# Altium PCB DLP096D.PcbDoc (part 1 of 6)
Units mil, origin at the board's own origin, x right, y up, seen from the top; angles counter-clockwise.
Board outline 4950 x 3159.45 mil, 8 copper layers (Top Layer, GND1, SIGNAL1, POWER1, POWER2, SIGNAL2, GND2, Bottom Layer), stack 60.4 mil thick; 328 components, 223 nets, 1380 pads, 856 vias.
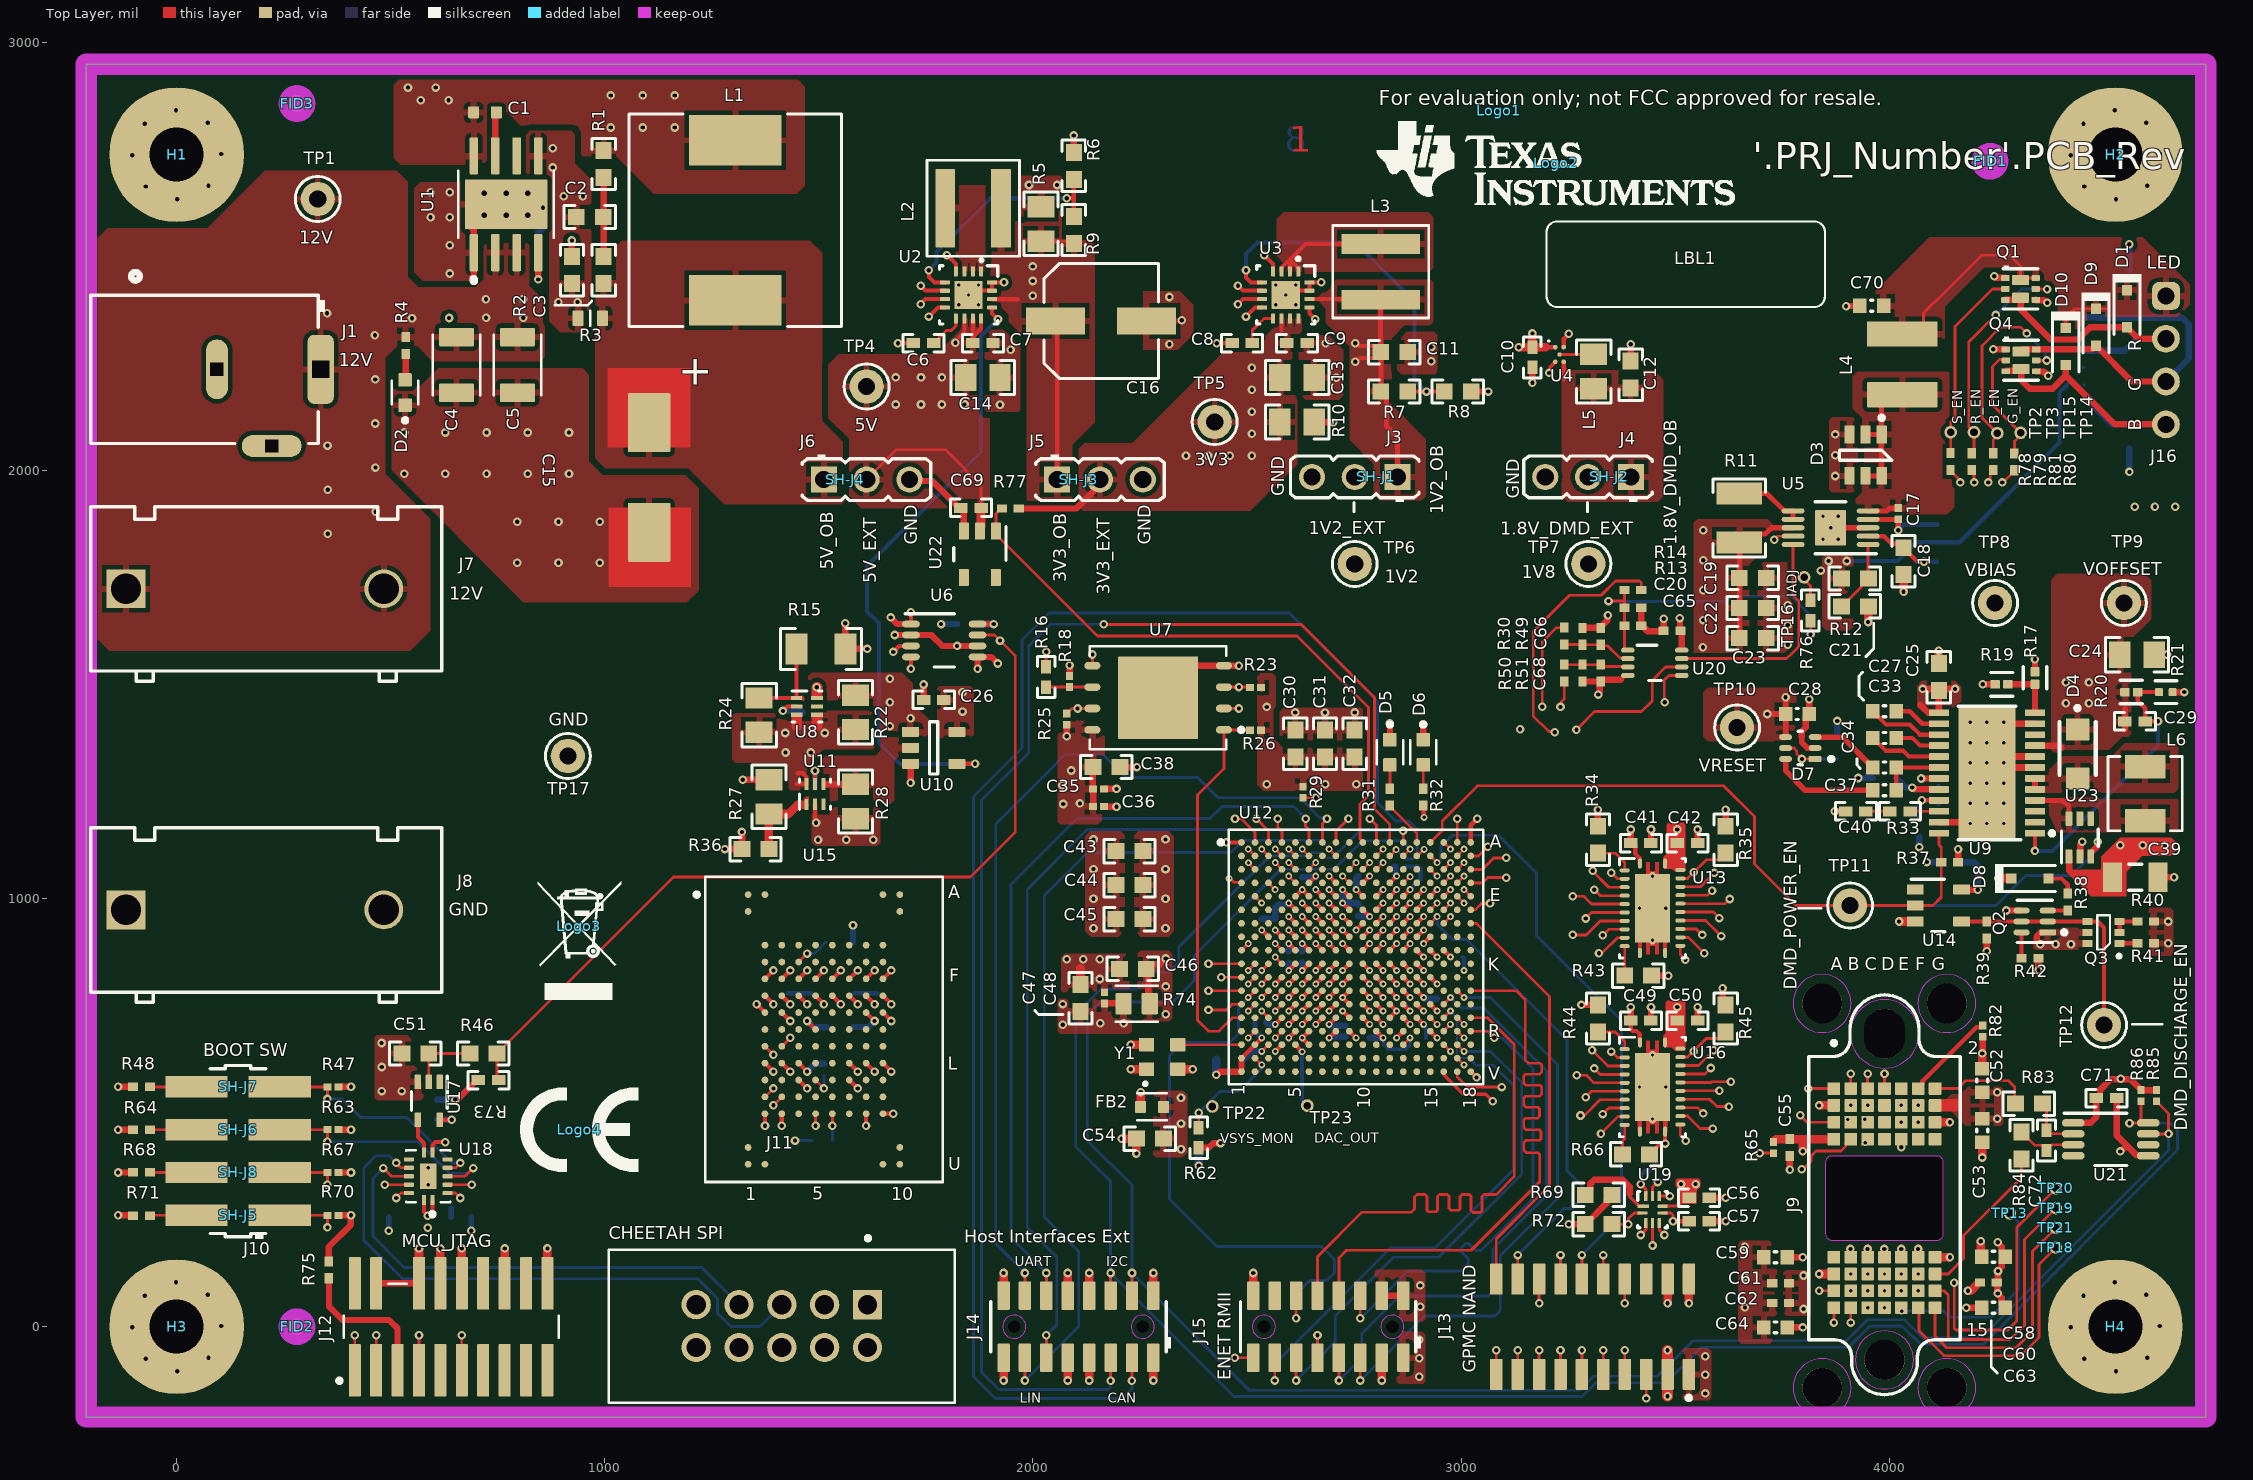
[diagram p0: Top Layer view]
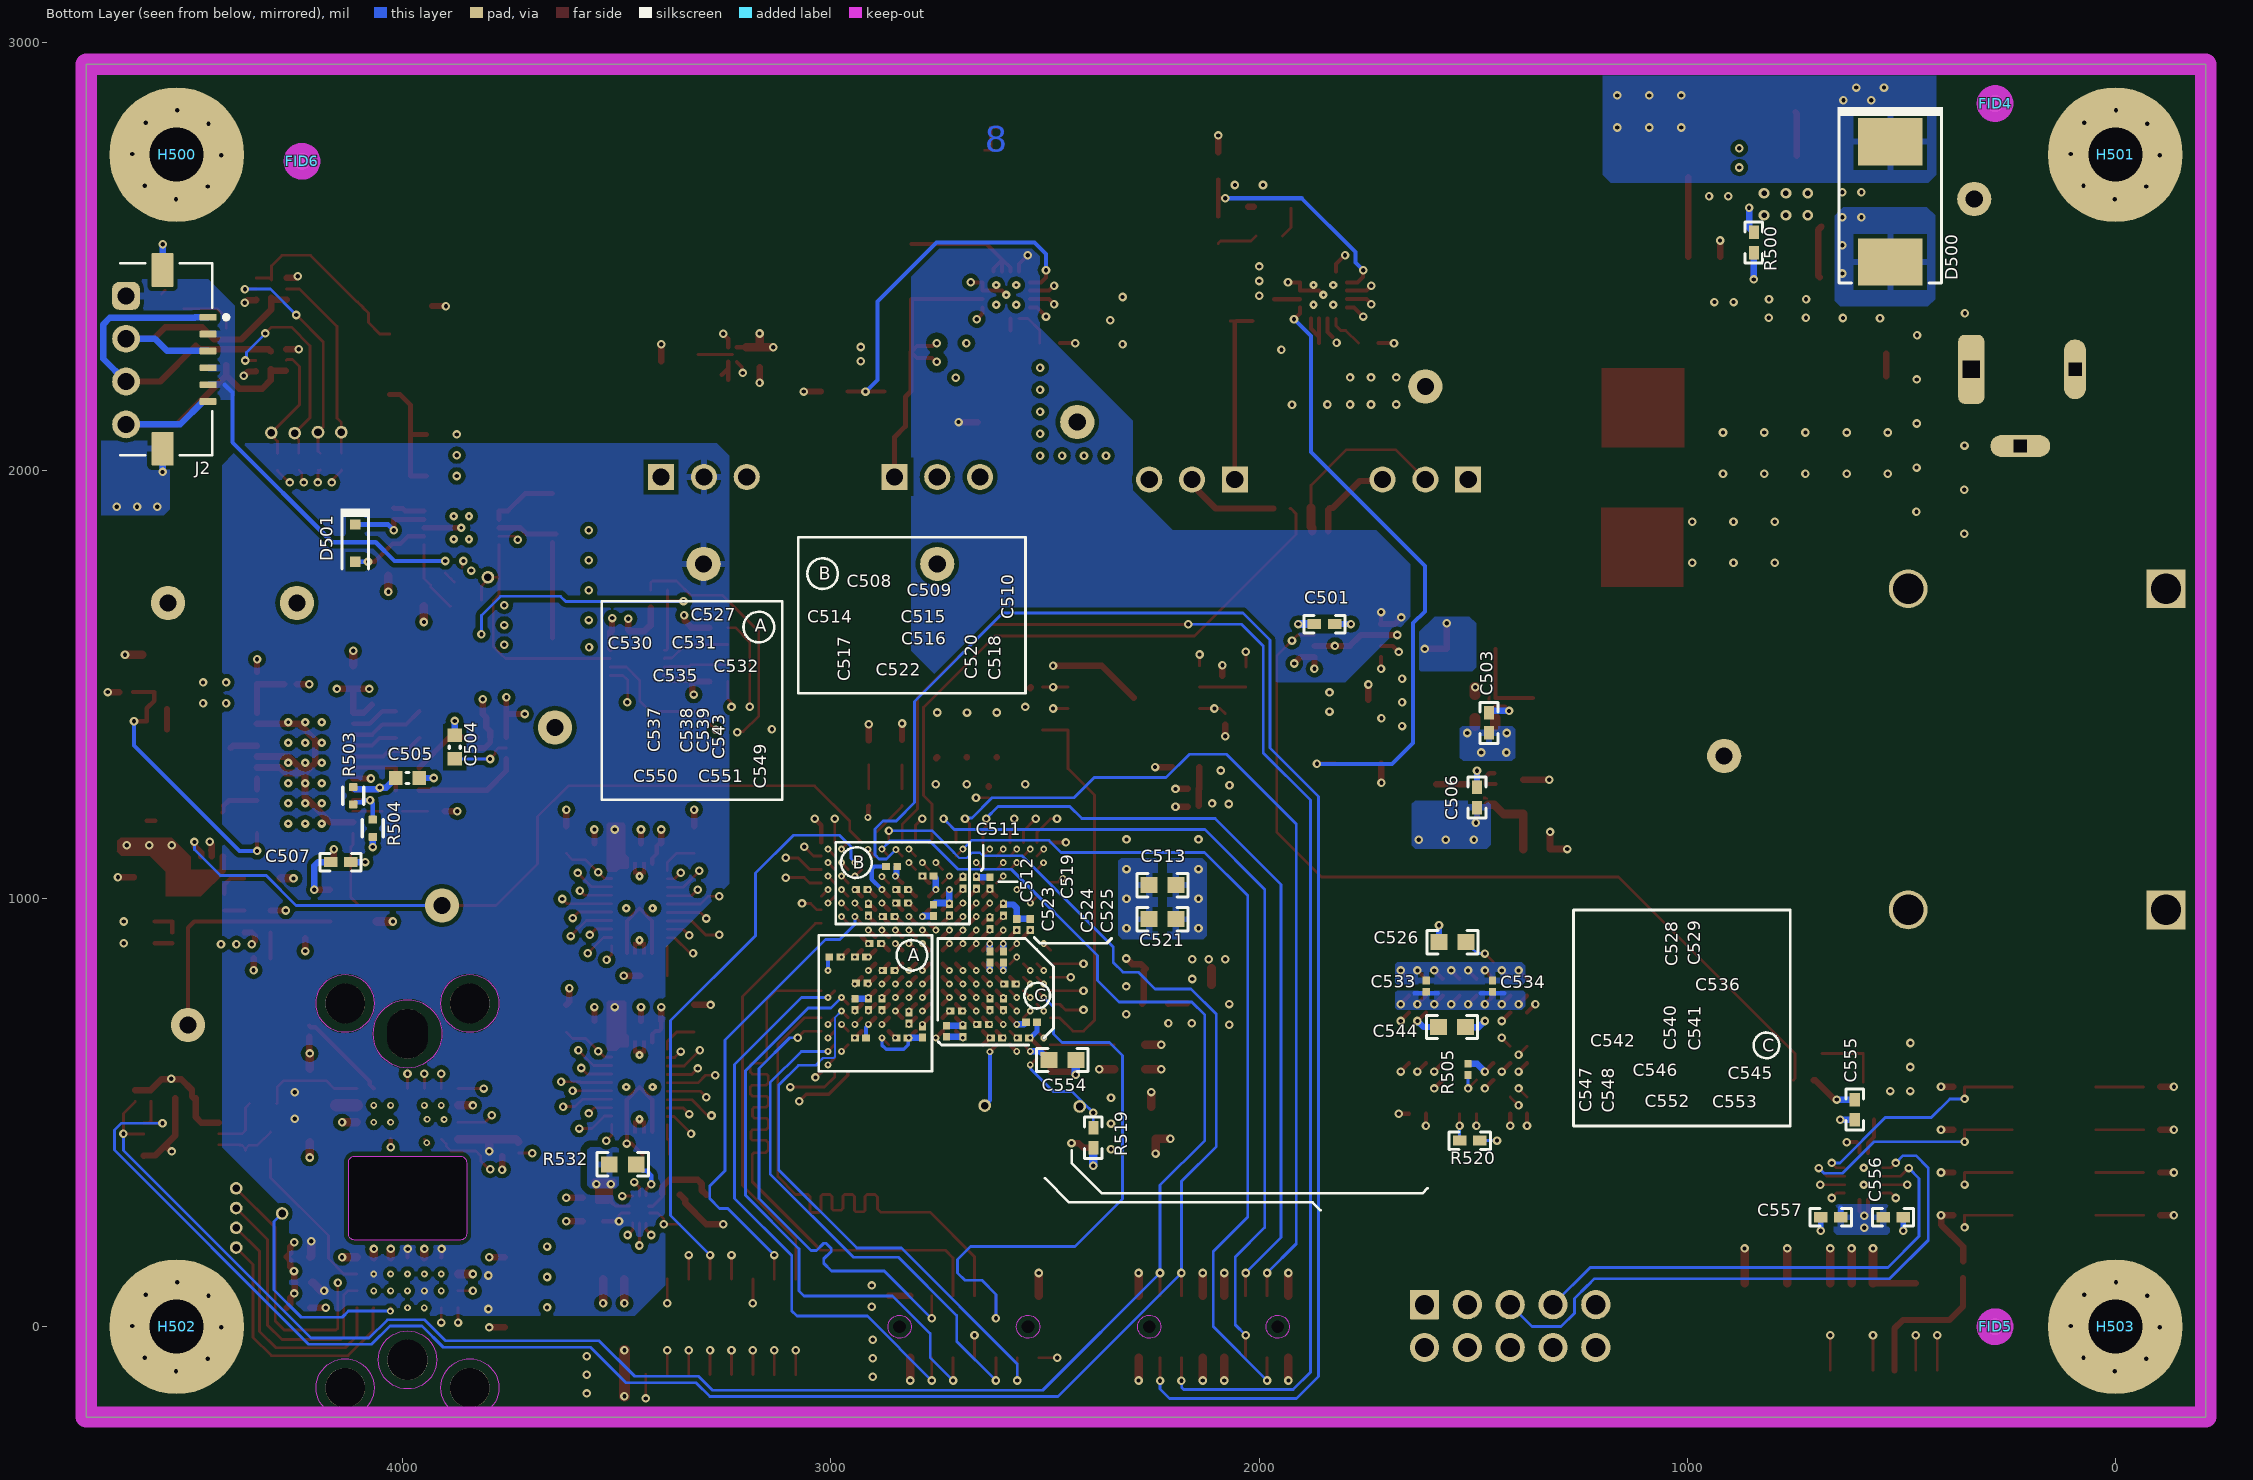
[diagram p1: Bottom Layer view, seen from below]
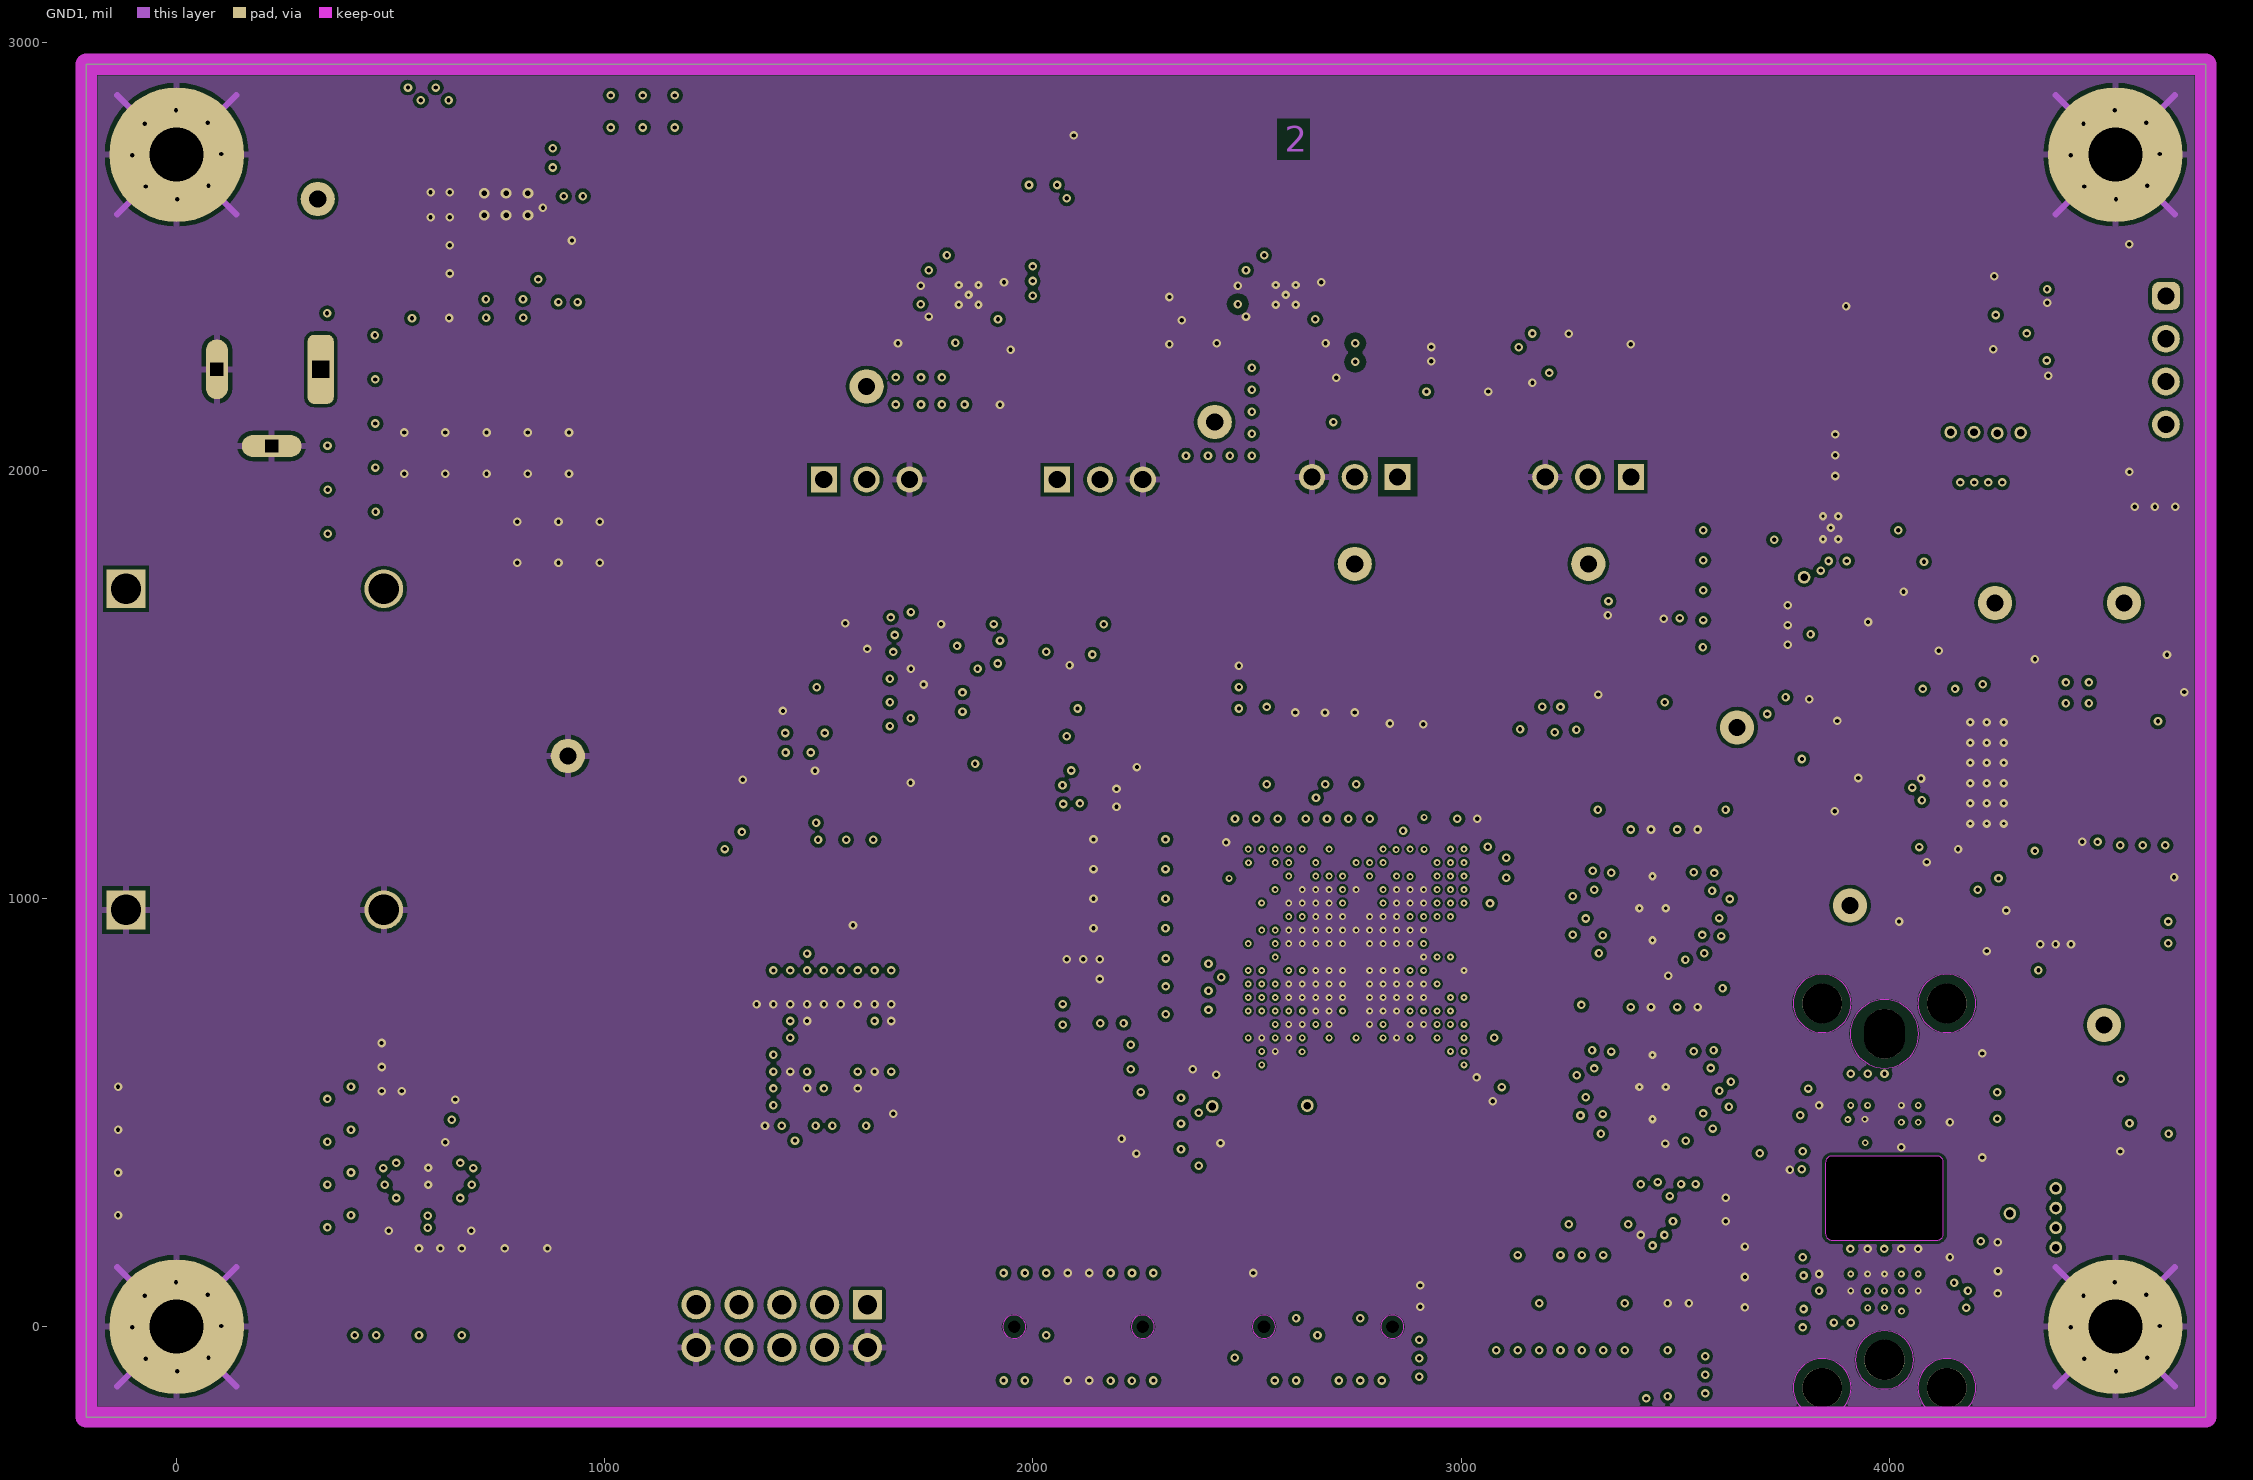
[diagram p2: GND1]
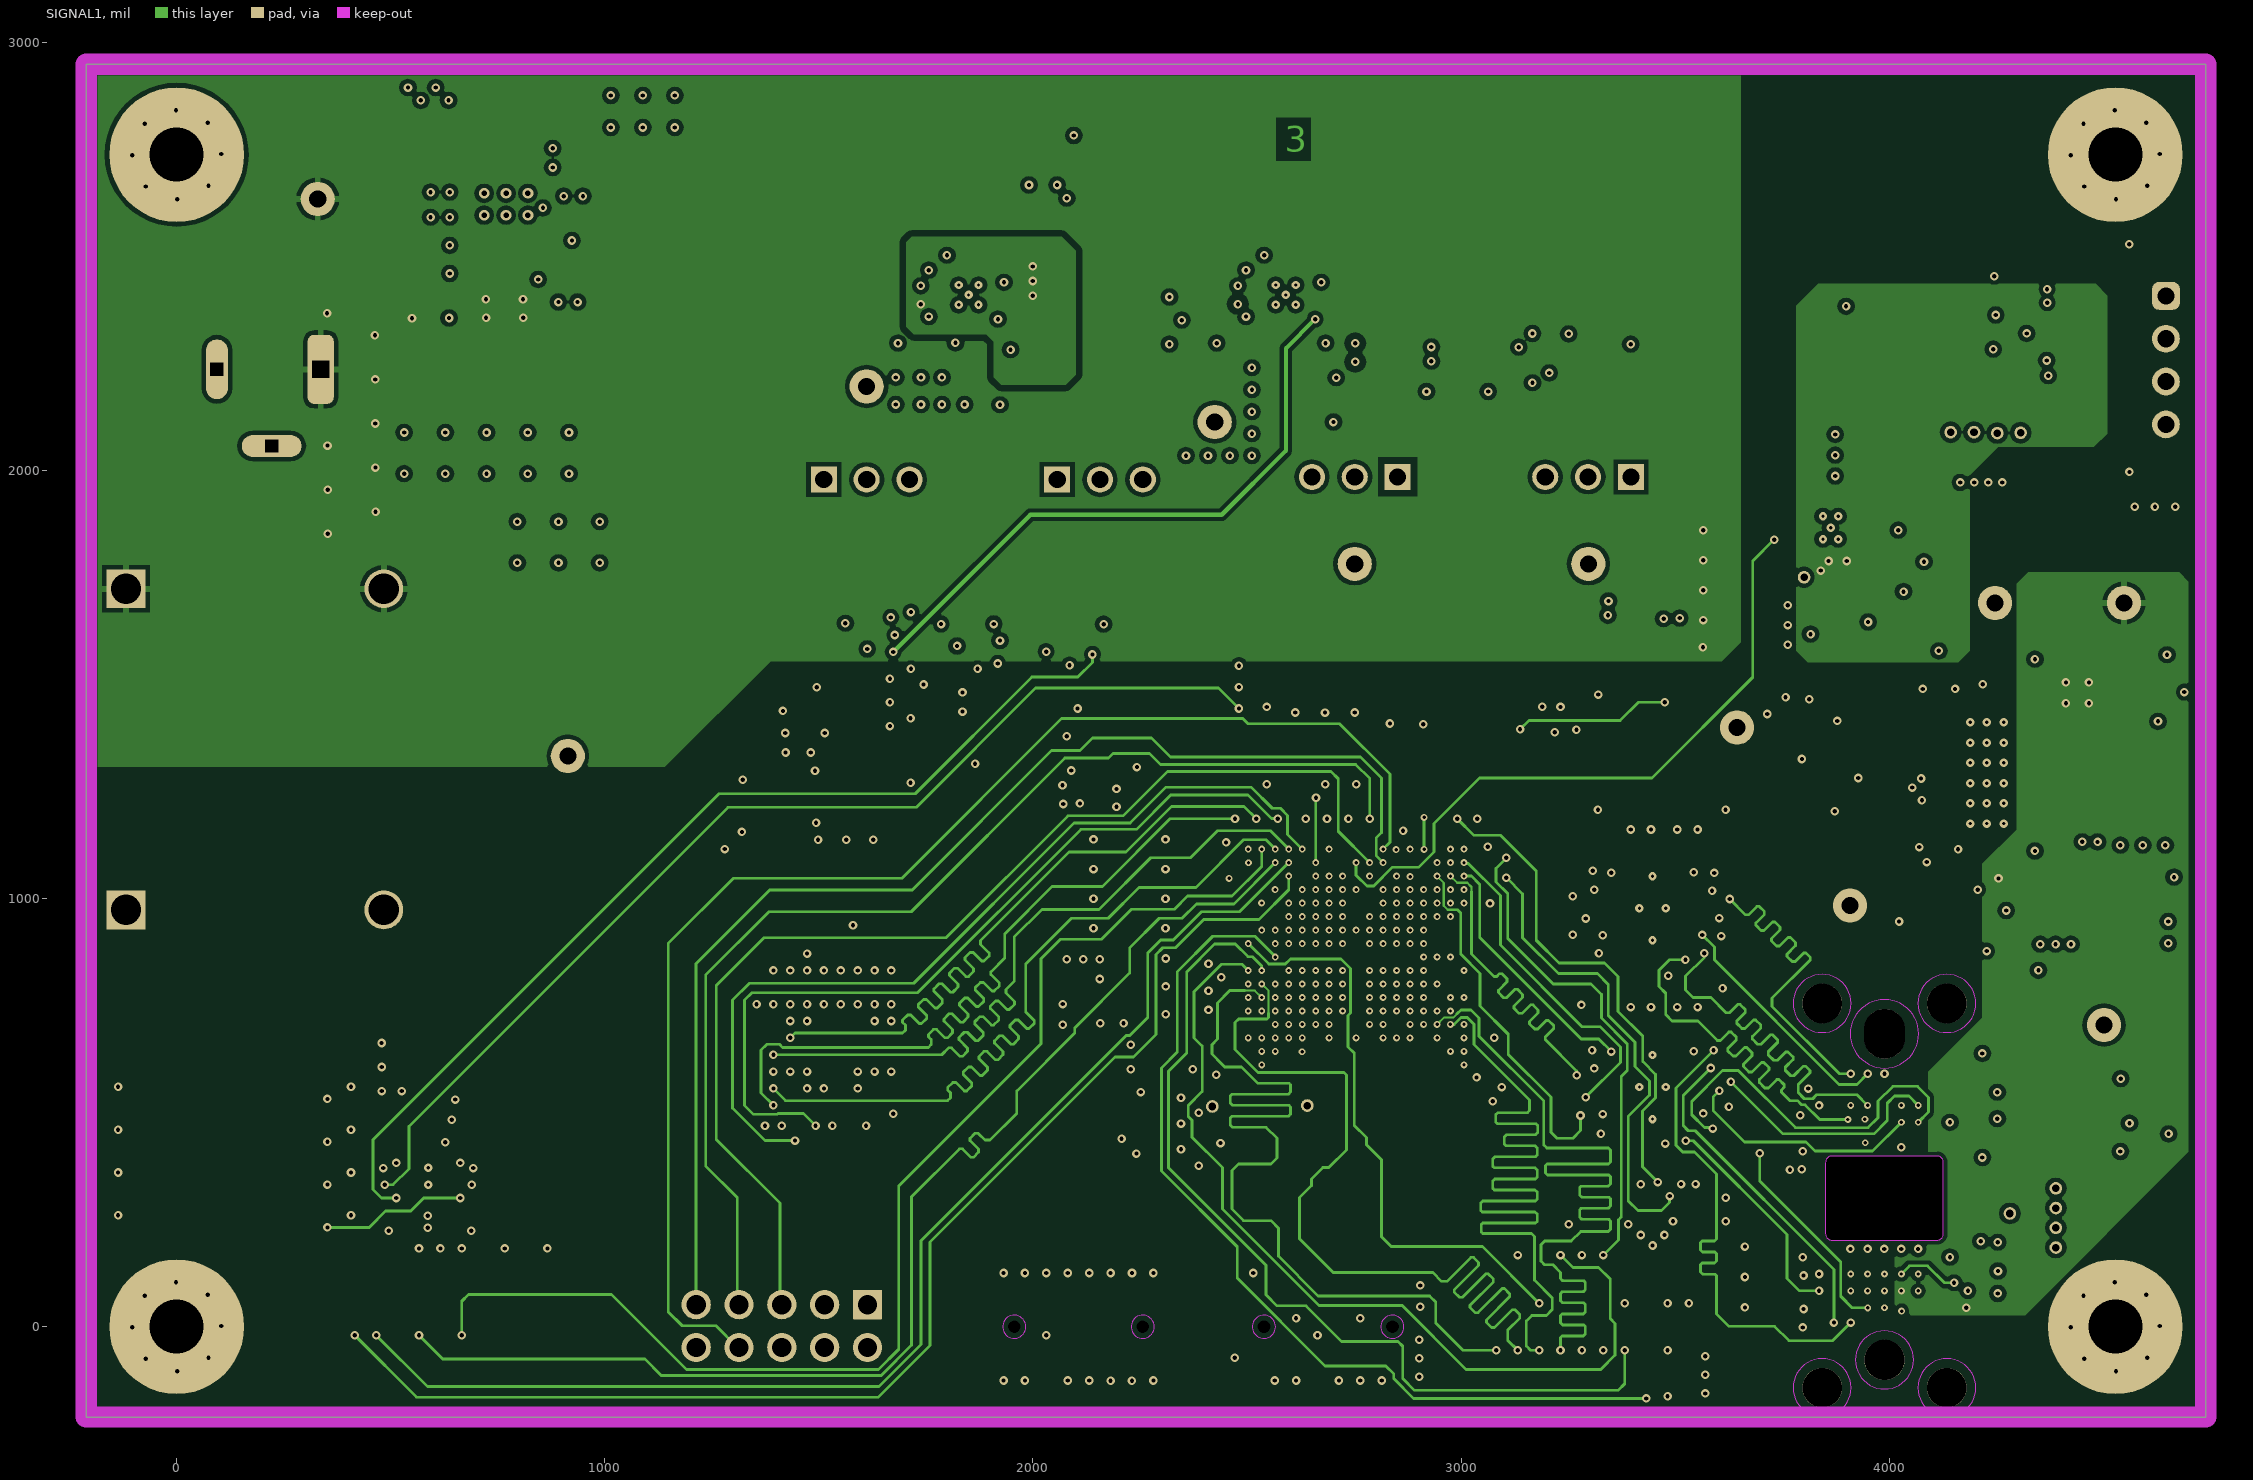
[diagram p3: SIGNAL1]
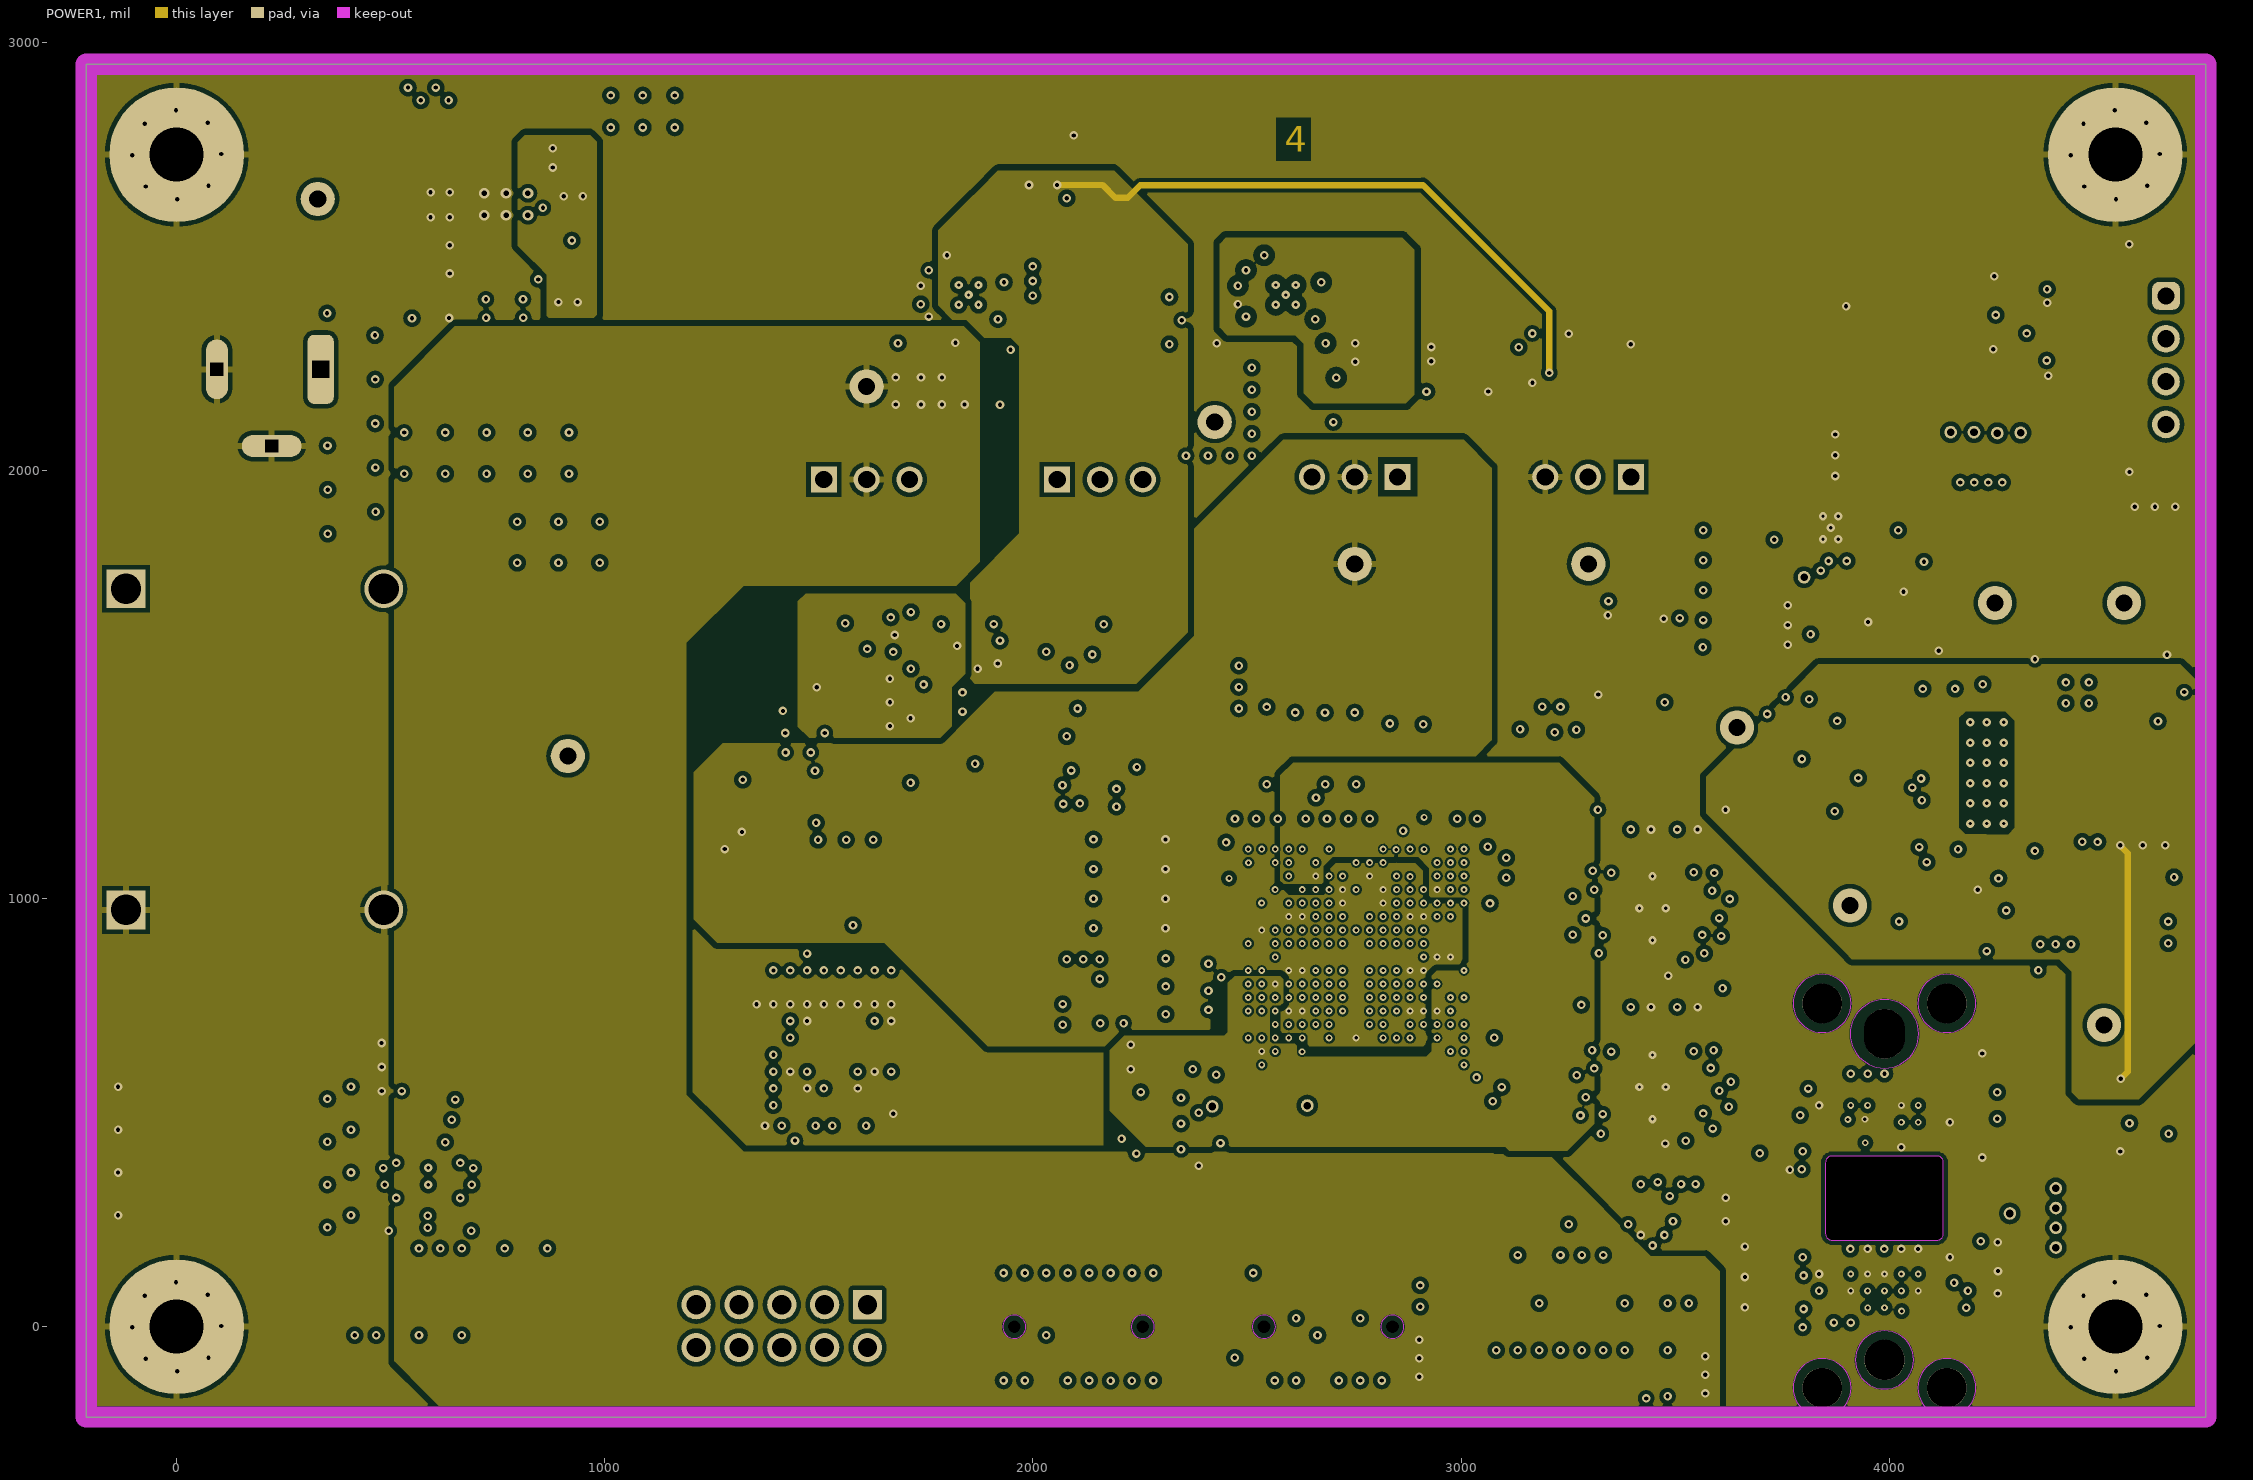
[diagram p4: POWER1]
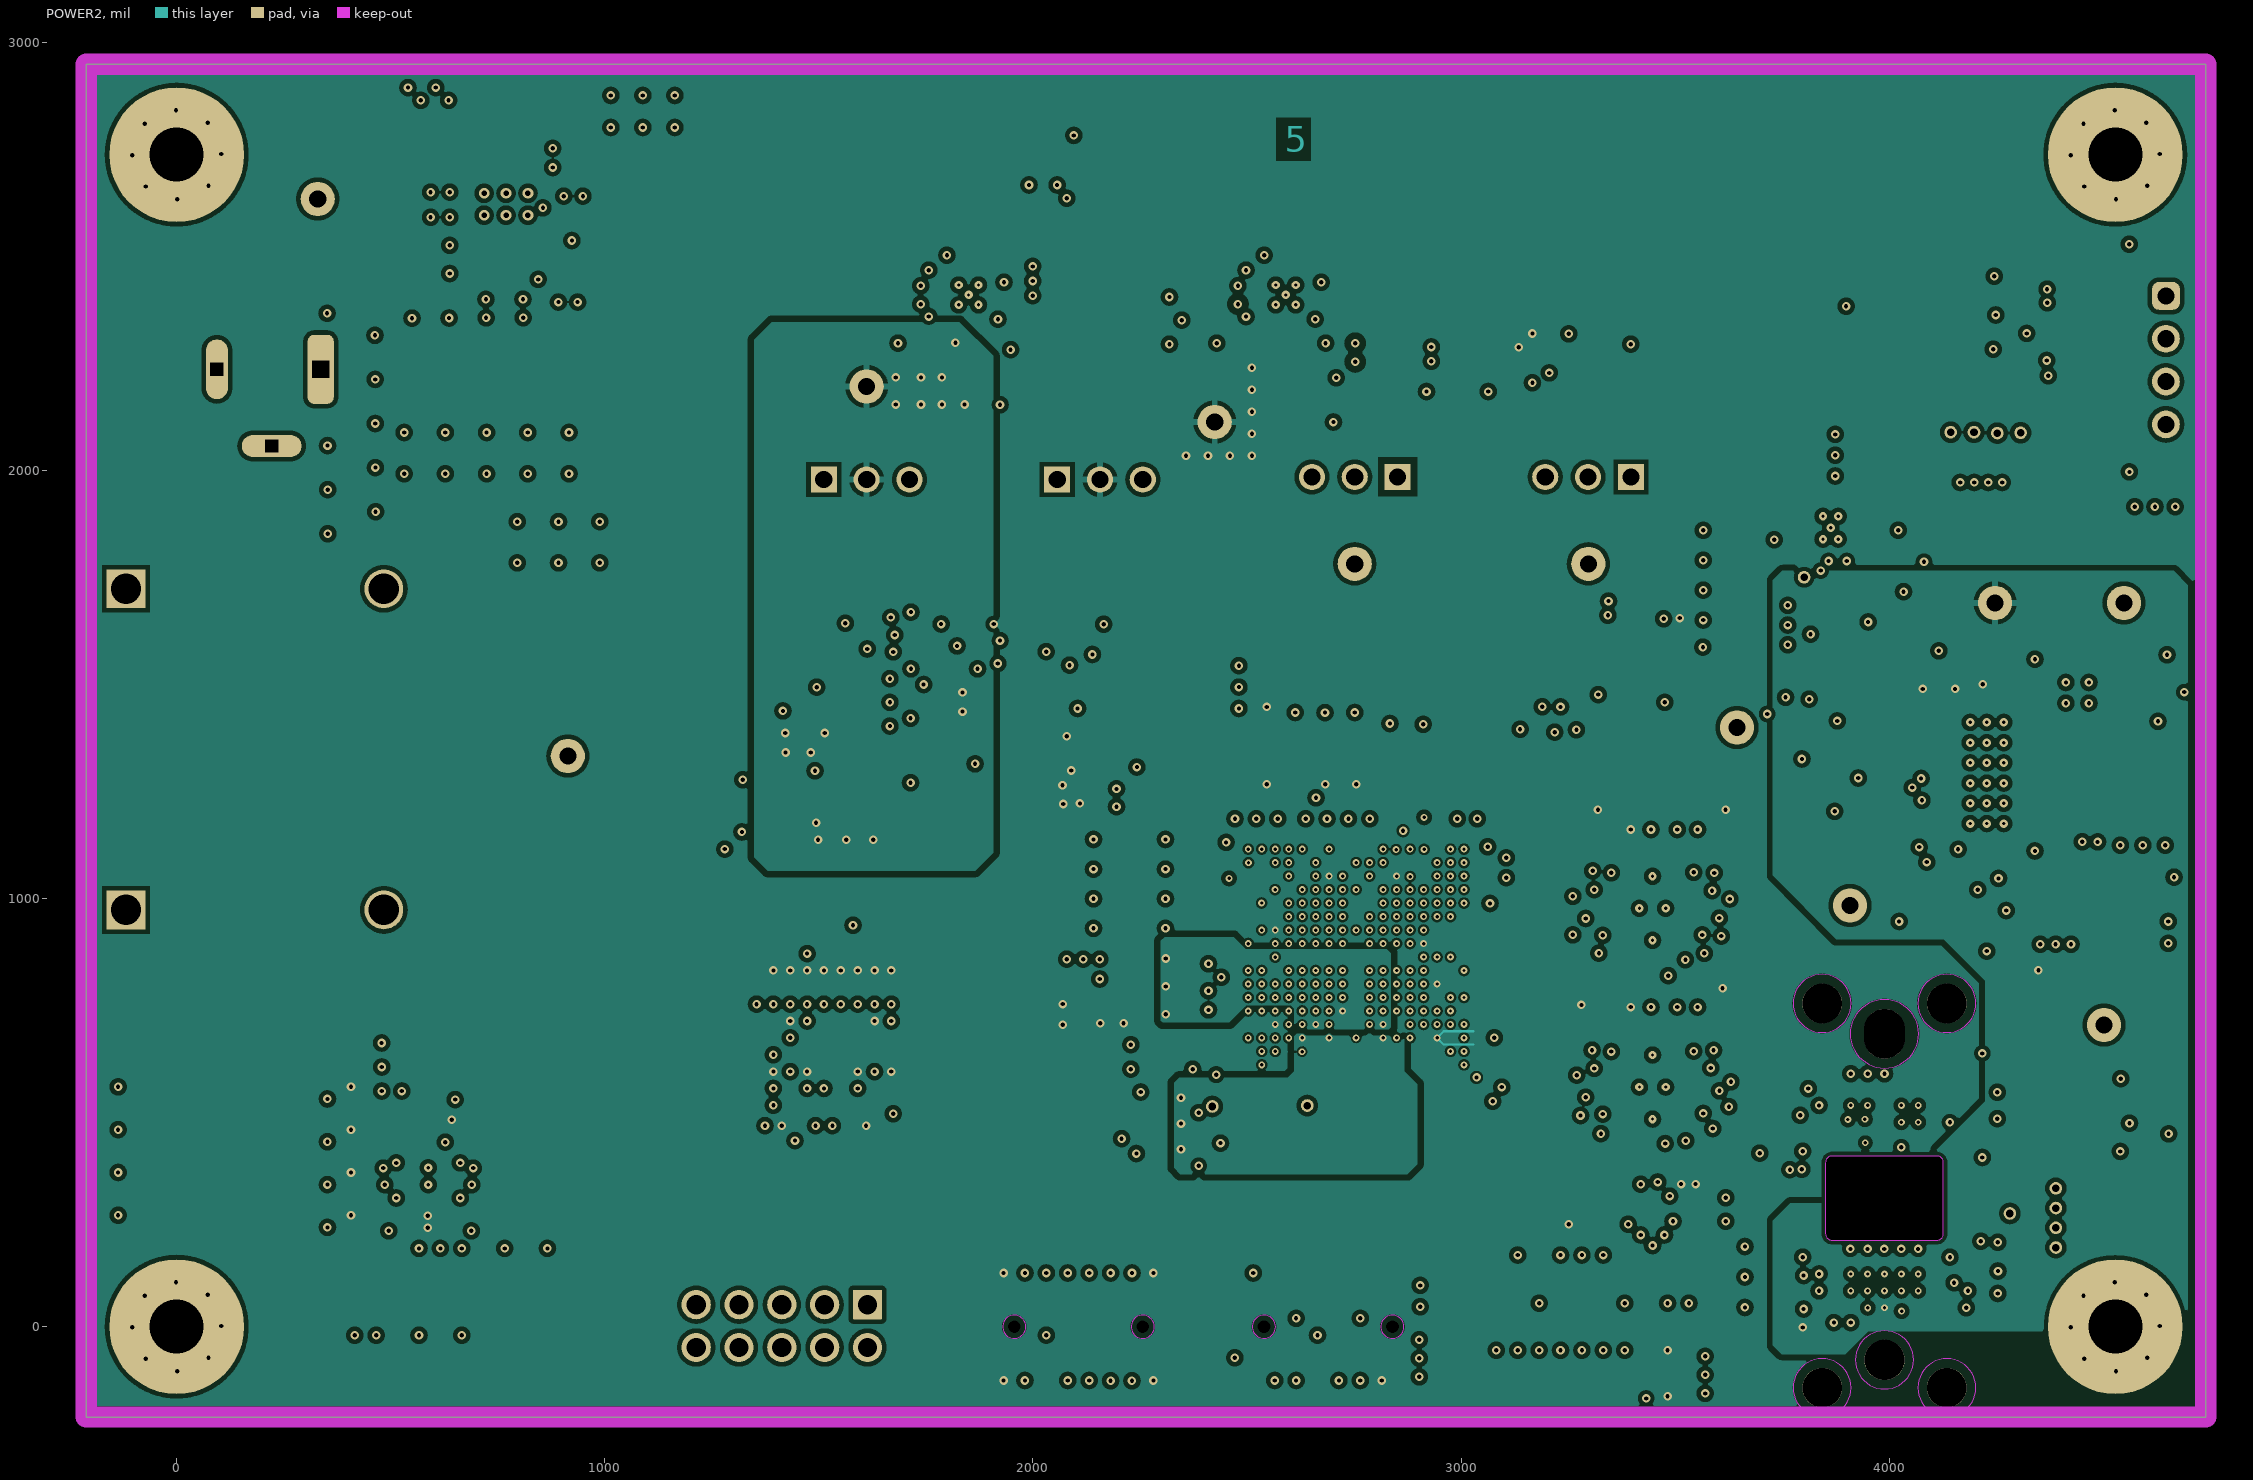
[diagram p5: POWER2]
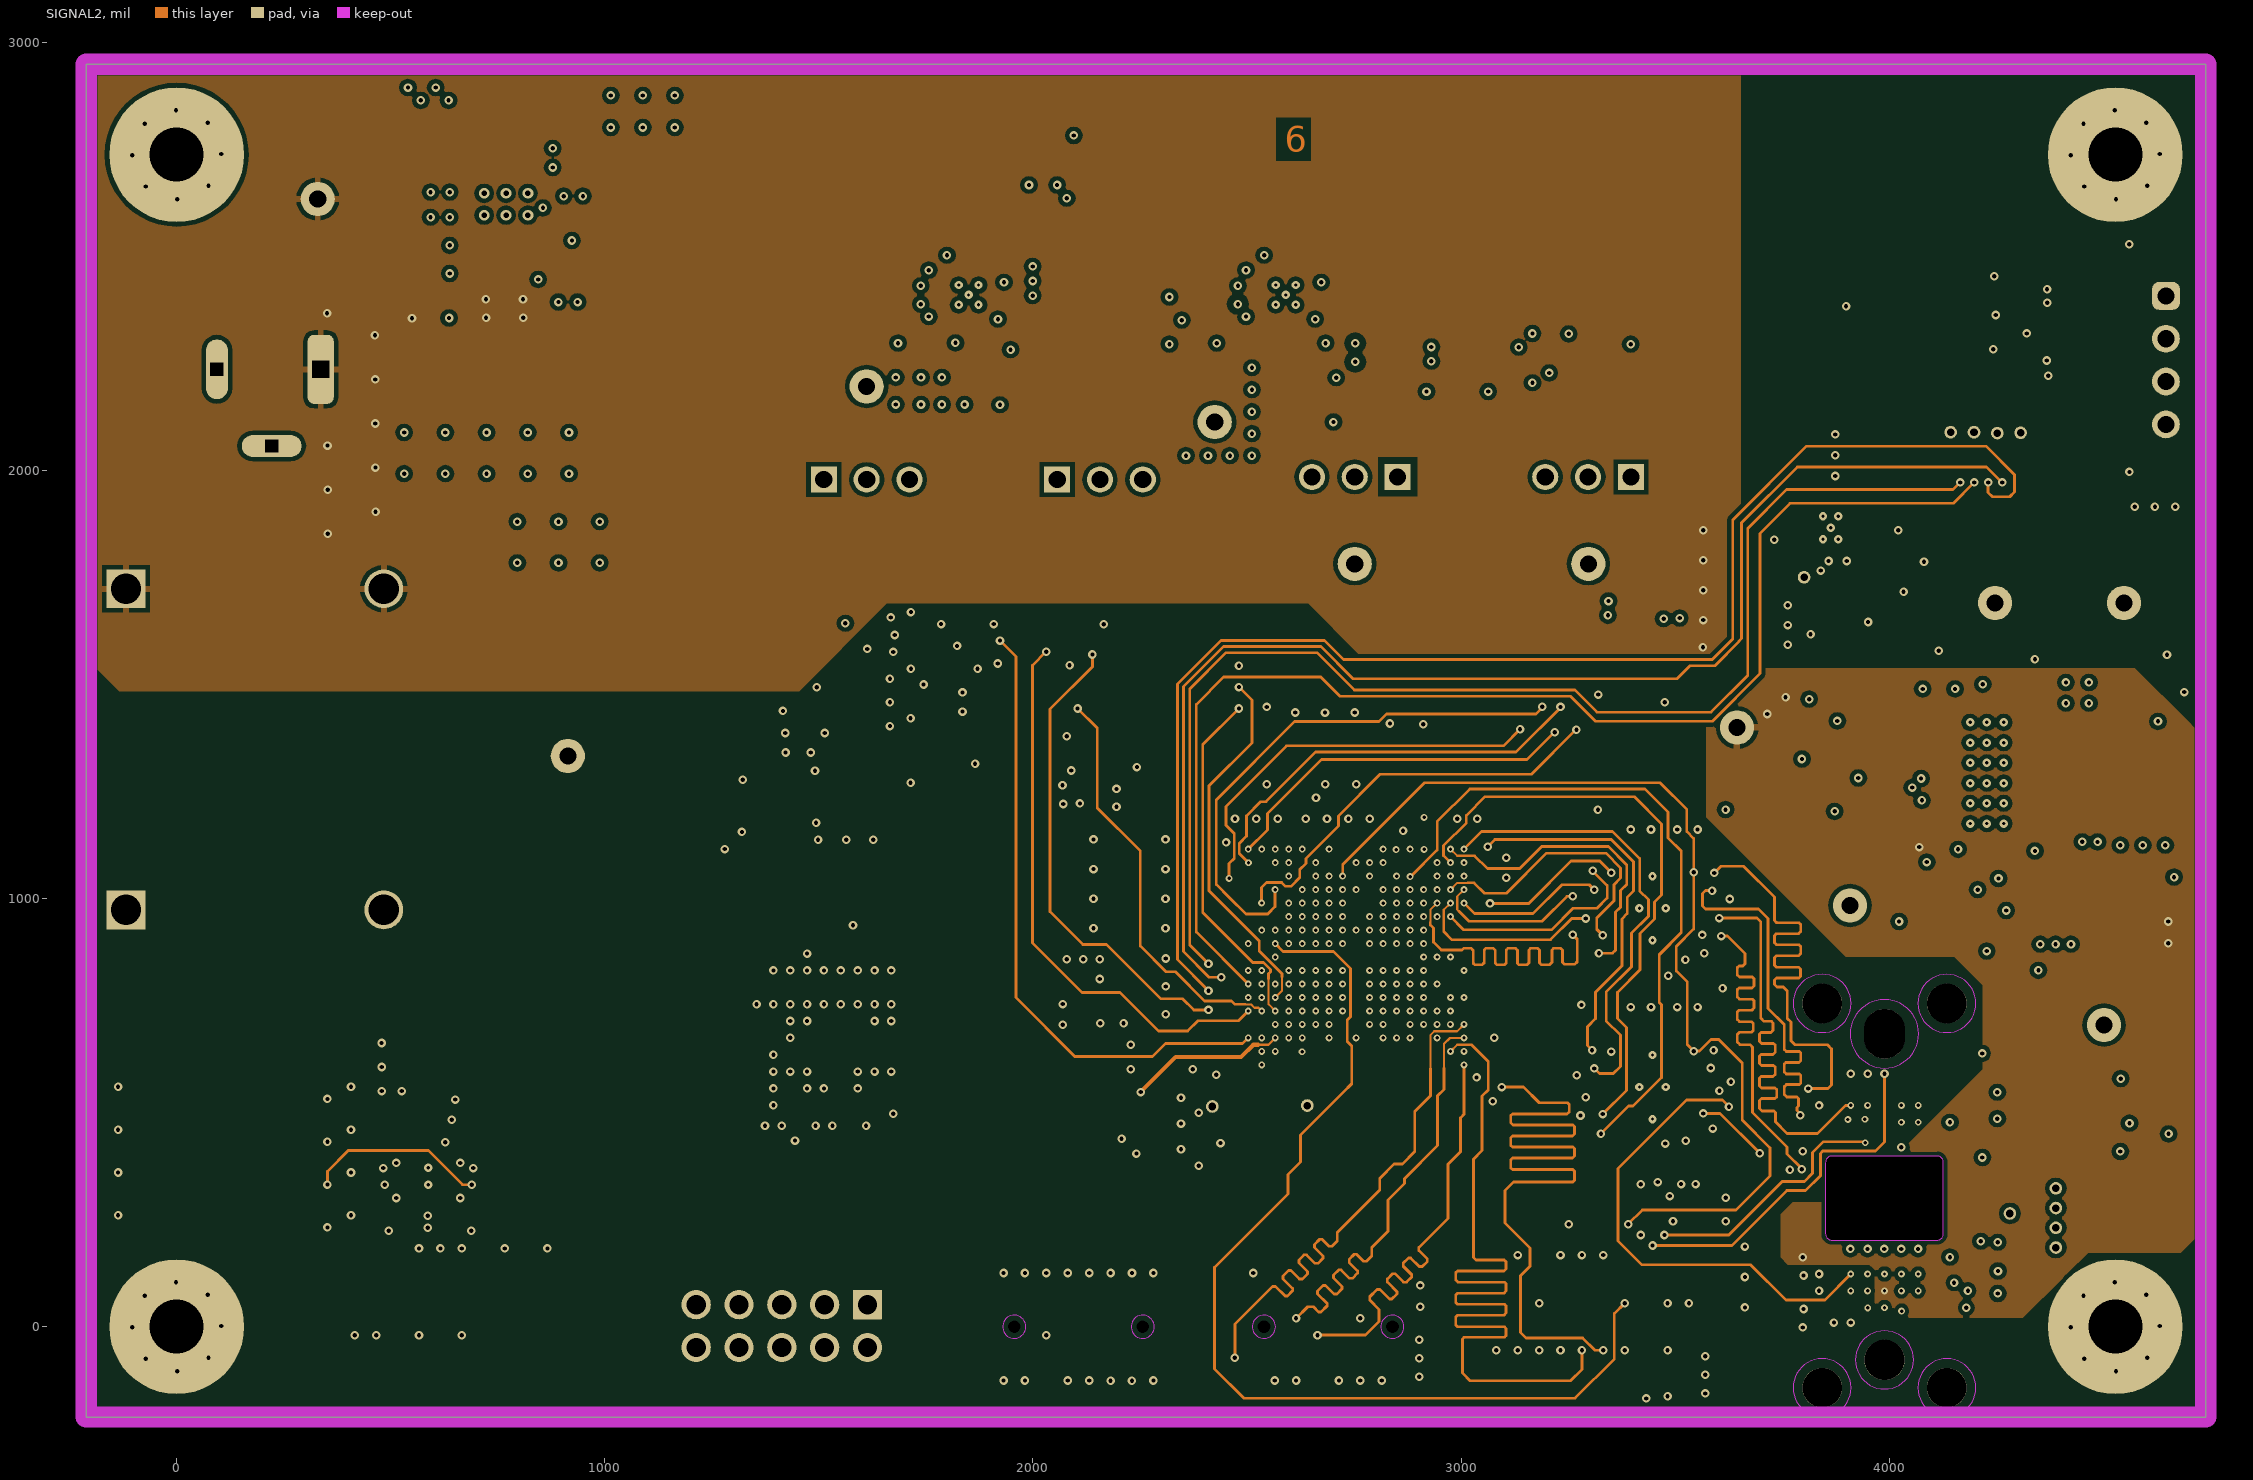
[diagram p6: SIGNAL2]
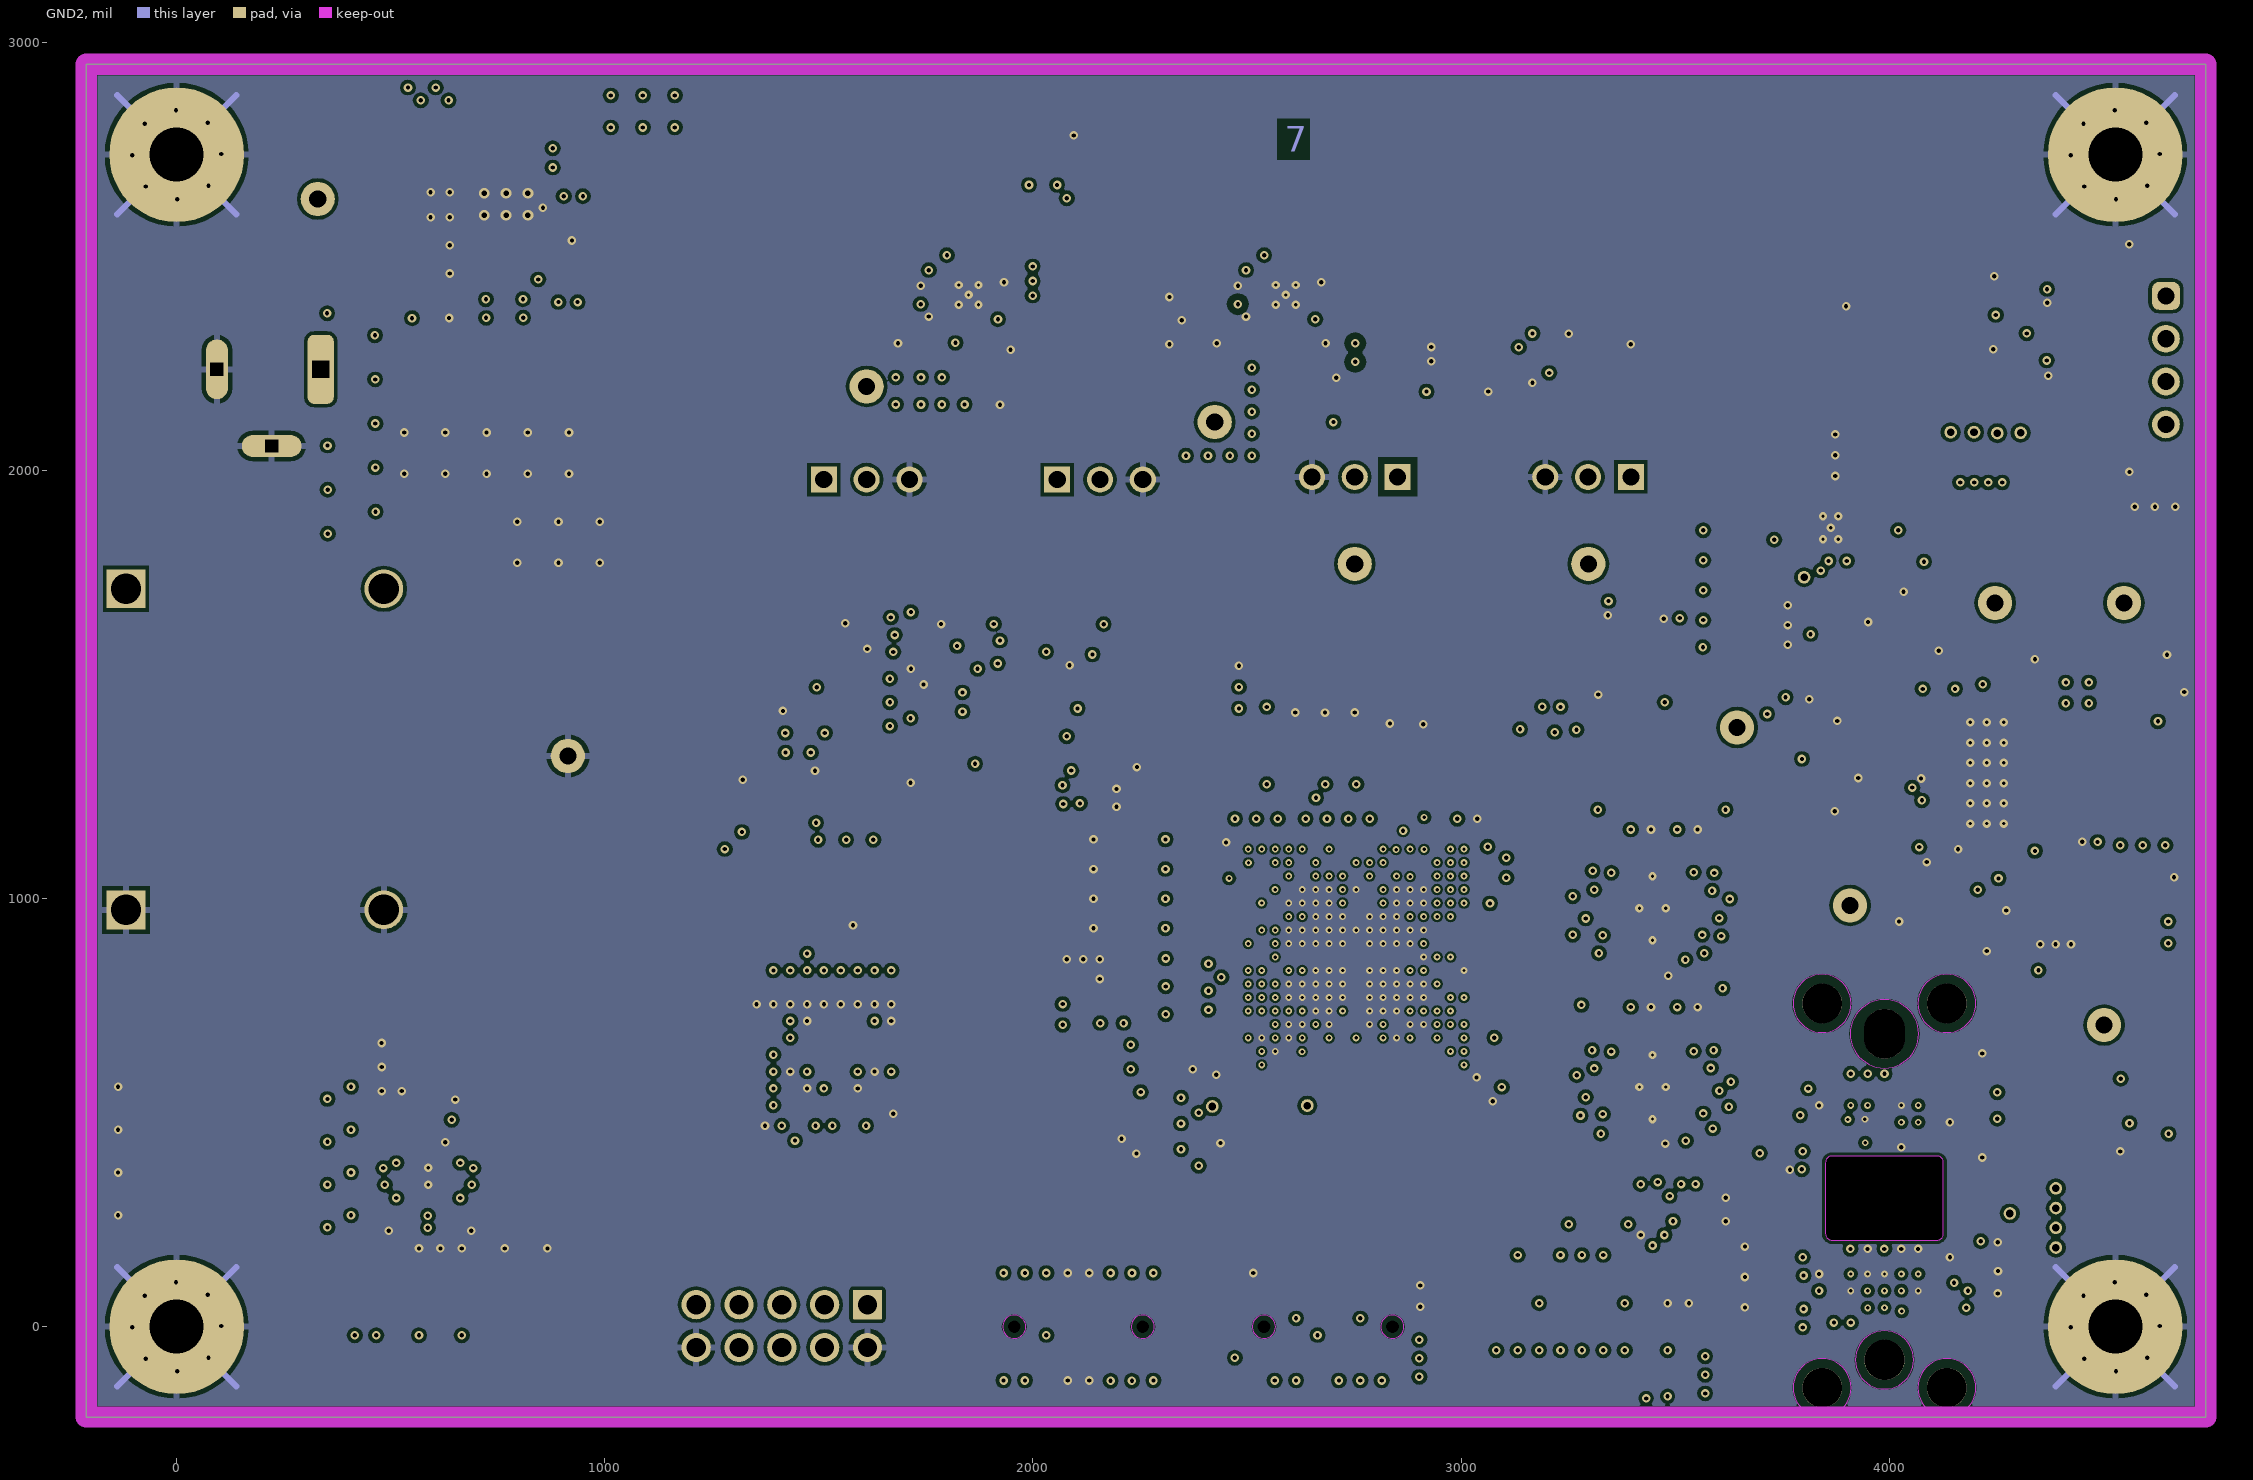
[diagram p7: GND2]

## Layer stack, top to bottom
Top Solder: solder mask 0.8, Solder Resist, Dk 3.5
Top Layer: signal copper 2.8
Dielectric 1: prepreg 4, FR-4 High Tg, Dk 4.1
GND1: signal copper 1.4
Dielectric 2: prepreg 8, FR-4 High Tg, Dk 4.1
SIGNAL1: signal copper 1.4
Dielectric 3: prepreg 8, FR-4 High Tg, Dk 4.1
POWER1: signal copper 1.4
Dielectric 4: core 6.4, FR-4 High Tg, Dk 4.8
POWER2: signal copper 1.4
Dielectric 5: prepreg 8, FR-4 High Tg, Dk 4.1
SIGNAL2: signal copper 1.4
Dielectric 6: prepreg 8, FR-4 High Tg, Dk 4.1
GND2: signal copper 1.4
Dielectric 7: prepreg 4, FR-4 High Tg, Dk 4.1
Bottom Layer: signal copper 2.8
Bottom Solder: solder mask 0.8, Solder Resist, Dk 3.5

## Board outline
-211,-211 4739,-211 4739,2948.45 -211,2948.45
cut-out: 3851.09,217.59 ccw(c3866.84,217.59) 3866.84,201.85 4110.93,201.85 ccw(c4110.93,217.59) 4126.68,217.59 4126.68,382.95 ccw(c4110.93,382.95) 4110.93,398.7 3866.84,398.7 ccw(c3866.84,382.95) 3851.09,382.95

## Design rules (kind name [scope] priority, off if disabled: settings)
AcuteAngle [All] p1: minimum=4.50000000000000E+0001 checktracksonly=FALSE
AssemblyTestPointUsage [All] p1: valid=2
BoardOutlineClearance BoardOutlineClearance_MountingHoles [OnCopper and InComponentClass('Mounting Holes')] p1: gap=39.37 ignorepadtopadclearanceinfootprint=FALSE
BoardOutlineClearance BoardOutlineClearance_Poly [OnCopper and IsPoly] p2: gap=25 ignorepadtopadclearanceinfootprint=FALSE
Clearance Clearance_FiducialMark [IsKeepOut and InComponentClass('FiducialMark') vs IsPad and InComponentClass('FiducialMark')] p1: gap=0 ignorepadtopadclearanceinfootprint=FALSE
Clearance "Clearance_Keepout to all" [isKeepout] p2: gap=1 ignorepadtopadclearanceinfootprint=FALSE
Clearance Clearance_Room1 [WithinRoom('RoomDefinition_1')] p3: gap=5 ignorepadtopadclearanceinfootprint=FALSE
Clearance Clearance_Voltage [not WithinRoom('RoomDefinition') and InNetClass('Voltage')] p4: gap=15 ignorepadtopadclearanceinfootprint=FALSE
Clearance "Clearance_GND layer" [InLayerClass('GND_Layer')] p5: gap=8 ignorepadtopadclearanceinfootprint=FALSE
Clearance "Clearance_Poly to Poly" [InPolygon vs InPolygon] p6: gap=15 ignorepadtopadclearanceinfootprint=FALSE
Clearance "Clearance_Poly to All" [InPolygon] p7: gap=10 ignorepadtopadclearanceinfootprint=FALSE
Clearance [All] p8: gap=7.87 ignorepadtopadclearanceinfootprint=FALSE
ComponentClearance ComponentClearance_MountingHoles_FiducialMarks [InComponentClass('Mounting Holes') vs InComponentClass('FiducialMark')] p1: gap=10 collisioncheckmode=3 verticalgap=10 showdistances=FALSE
ComponentClearance ComponentClearance_Shunt [InComponentClass('Header') vs InComponentClass('Shunt')] p2: gap=0 collisioncheckmode=3 verticalgap=0 showdistances=FALSE
ComponentClearance ComponentClearance_Logo [InComponentClass('Logo')] p3: gap=10 collisioncheckmode=3 verticalgap=10 showdistances=FALSE
ComponentClearance ComponentClearance_ScrewToNut [(HasFootprint('NY PMS 440 0025 PH')) vs (HasFootprint('Keystone_1902C'))] p4: gap=5 collisioncheckmode=3 verticalgap=10 showdistances=FALSE
ComponentClearance ComponentClearance_MountingHoles [InComponentClass('Mounting Holes')] p5: gap=100 collisioncheckmode=3 verticalgap=100000 showdistances=FALSE
ComponentClearance ComponentClearance_SmallPassives [HasFootprint('0201*') or HasFootprint('0402*') or HasFootprint('0508') or HasFootprint('0603*') or HasFootprint('0612') or HasFootprint('0805*') or HasFootprint('0815*') or HasFootprint('0830*') or HasFootprint('1206*') or HasFootprint('1210*') or HasFootprint('1808*') or HasFootprint('1812*') or HasFootprint('1825*') or HasFootprint('2010*') or HasFootprint('2220*') or HasFootprint('2225*') or HasFootprint('2512*') or HasFootprint('2728*') or HasFootprint('3518*') vs HasFootprint('0201*') or HasFootprint('0402*') or HasFootprint('0508') or HasFootprint('0603*') or HasFootprint('0612') or HasFootprint('0805*') or HasFootprint('0815*') or HasFootprint('0830*') or HasFootprint('1206*') or HasFootprint('1210*') or HasFootprint('1808*') or HasFootprint('1812*') or HasFootprint('1825*') or HasFootprint('2010*') or HasFootprint('2220*') or HasFootprint('2225*') or HasFootprint('2512*') or HasFootprint('2728*') or HasFootprint('3518*')] p6: gap=10 collisioncheckmode=3 verticalgap=10 showdistances=FALSE
ComponentClearance ComponentClearance_THtoSMT [IsThruComponent vs IsSMTComponent] p7: gap=10 collisioncheckmode=3 verticalgap=30 showdistances=FALSE
ComponentClearance ComponentClearance_THtoTH [IsThruComponent vs IsThruComponent] p8: gap=10 collisioncheckmode=3 verticalgap=30 showdistances=FALSE
ComponentClearance [All] p9: gap=10 collisioncheckmode=3 verticalgap=10 showdistances=FALSE
DiffPairsRouting [All] p1: maxlimit=100 minlimit=10 mostfreqgap=10 toplayer_minwidth=15 toplayer_maxwidth=15 toplayer_prefwidth=15 midlayer1_minwidth=15 midlayer1_maxwidth=15 midlayer1_prefwidth=15 midlayer2_minwidth=15 midlayer2_maxwidth=15 midlayer2_prefwidth=15 midlayer3_minwidth=15 midlayer3_maxwidth=15 midlayer3_prefwidth=15 midlayer4_minwidth=15 midlayer4_maxwidth=15 midlayer4_prefwidth=15 midlayer5_minwidth=15 midlayer5_maxwidth=15 midlayer5_prefwidth=15 midlayer6_minwidth=15 midlayer6_maxwidth=15 midlayer6_prefwidth=15 bottomlayer_minwidth=15 bottomlayer_maxwidth=15 bottomlayer_prefwidth=15 maxuncoupledlength=1000
FabricationTestPointUsage TestPointUsage [All] p1: valid=2 allowmultiple=FALSE
FabricationTestpoint Testpoint [All] p1: side=3 testpointundercomponent=TRUE minsize=40 maxsize=100 preferedsize=60 minholesize=0 maxholesize=40 preferedholesize=32 testpointgrid=1 allowsidetop=TRUE allowsidebottom=TRUE usegrid=TRUE gridtolerance=0.01
FanoutControl Fanout_LCC [IsLCC] p1: bgadir=Out bgaviamode=Centered fanoutstyle=Auto fanoutdirection=Alternating viagrid=1 // Fanout_LCC (Default Rule)
FanoutControl Fanout_BGA [IsBGA] p2: bgadir=Out bgaviamode=Centered fanoutstyle=Auto fanoutdirection=Alternating viagrid=1 // Fanout_BGA (Default Rule)
FanoutControl Fanout_Default [All] p4: bgadir=Out bgaviamode=Centered fanoutstyle=Auto fanoutdirection=Alternating viagrid=1 // Fanout_Default (Default Rule)
FanoutControl Fanout_Small [(CompPinCount < 5)] p5: bgadir=Out bgaviamode=Centered fanoutstyle=Auto fanoutdirection=OutThenIn viagrid=1 // Fanout_Small (Default Rule)
HoleSize [All] p1: absolutevalues=TRUE maxlimit=251 minlimit=7.87 maxpercent=80.000 minpercent=20.000
MinimumAnnularRing MinimumAnnularRing_ThermalPadVias [IsVia and InAnyComponent] p1: minimumring=5.91
MinimumAnnularRing [All] p2: minimumring=3.9
MinimumSolderMaskSliver MinimumSolderMaskSliver_Logo [InComponentClass('Logo') vs InComponentClass('Logo')] p1: minsoldermaskwidth=0.7
MinimumSolderMaskSliver [All] p2: minsoldermaskwidth=3.94
PlaneConnect [All] p1: planeconnectstyle=Relief reliefexpansion=10 reliefentries=4 reliefconductorwidth=10 reliefairgap=10
PolygonConnect [All] p1: thpad.connectstyle=Relief thpad.reliefconductorwidth=15 thpad.reliefentries=4 thpad.polygonreliefangle="90 Angle" thpad.airgapwidth=10 smdpad.connectstyle=Relief smdpad.reliefconductorwidth=15 smdpad.reliefentries=4 smdpad.polygonreliefangle="90 Angle" smdpad.airgapwidth=10 via.connectstyle=Direct via.reliefconductorwidth=10 via.reliefentries=4 via.polygonreliefangle="90 Angle" via.airgapwidth=10
RoomDefinition RoomDefinition_1 [False vs False] p1: confinementstyle=ConfineIn formatcopy=TRUE lockcomponents=FALSE outline 2459.64,1167.9 3054.79,1167.9 3054.79,559.63 2459.64,559.63
RoutingVias ThermalPadVias [IsVia and InAnyComponent] p1: holewidth=7.87 width=19.68 viastyle="Through Hole" minholewidth=7.87 minwidth=19.68 maxholewidth=12.99 maxwidth=23.62
RoutingVias [All] p2: holewidth=8 width=34 viastyle="Through Hole" minholewidth=7.87 minwidth=16 maxholewidth=40 maxwidth=65
SilkToBoardRegionClearance [Not ((IsComment or IsDesignator) And (Hide <> 'False')) and not InRegion(1000,500,4000,800)] p1:
SilkToSilkClearance SilkToSilkClearance_Pb-FreeLogo [(HasFootprint('Pb-Free_Overlay_Medium') OR HasFootprint('Pb-Free_Overlay_Small')) vs (HasFootprint('Pb-Free_Overlay_Medium') OR HasFootprint('Pb-Free_Overlay_Small'))] p1: silktosilkclearance=0
SilkToSilkClearance [All] p2: silktosilkclearance=3.94
SilkToSolderMaskClearance SilkToComponentPadClearance [(IsPad or IsFill or IsRegion) and InAnycomponent] p1: minsilkscreentomaskgap=3 clearancetoexposedcopper=TRUE
SilkToSolderMaskClearance "Silk to Solder Mask Opening" [All] p2: minsilkscreentomaskgap=3.94 clearancetoexposedcopper=FALSE
SolderMaskExpansion SolderMaskExpansion_NPTH [IsThruPin And (PadIsPlated = 'False')] p1: expansion=5 istentingtop=FALSE soldermaskfromhole=TRUE
SolderMaskExpansion SolderMaskExpansion_PTH [IsThruPin] p2: expansion=2.5 istentingtop=FALSE
SolderMaskExpansion [All] p3: expansion=0 istentingtop=FALSE
UnRoutedNet [All] p1: checkbadconnections=TRUE
Width Width_50OHM [InNetClass('50 OHM')] p1: maxlimit=6.5 minlimit=5 preferedwidth=6.5
Width [All] p2: maxlimit=100 minlimit=5 preferedwidth=15 checkconnectedcopper=TRUE
14 further rules are at their usual default settings.

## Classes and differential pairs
net class Voltage: 1V2_OB NetL3_1
net class POWER: 1V2_OB NetL3_1
component class Header: J3 J4 J5 J6 J10 J16
component class DLP096D_System_Power: C1 C2 C3 C4 C5 C6 C7 C8 C9 C10 C11 C12 C13 C14 C15 C16 C26 C501 C503 C506 D2 D500 J1 J3 J4 J5 J6 J7 J8 L1 L2 L3 L5 R1 R2 R3 R4 R5 R6 R7 R8 R9 R10 R15 R22 R24 R27 R28 R36 R500 TP1 TP4 TP5 TP6 TP7 TP17 U1 U2 U3 U4 U6 U8 U10 U11
component class DLP096D_SoC_Power_Clock: C30 C31 C32 C43 C44 C45 C46 C47 C48 C54 C508 C509 C510 C511 C512 C513 C514 C515 C516 C517 C518 C519 C520 C521 C522 C523 C524 C525 C527 C528 C529 C530 C531 C532 C535 C536 C537 C538 C539 C540 C541 C542 C543 C545 C546 C547 C548 C549 C550 C551 C552 C553 C554 FB2 R62 R73 R74 R519 TP22 TP23 U12 Y1
component class DLP096D_SoC_Memory: C35 C36 C38 C51 C526 C533 C534 C544 C555 C556 C557 J10 R16 R18 R23 R25 R26 R29 R46 R47 R48 R63 R64 R67 R68 R70 R71 R505 R520 U7 U15 U17 U18
component class DLP096D_LED_Driver: C17 C18 C19 C20 C21 C22 C23 C65 C66 C68 C70 D1 D3 D9 D10 D501 J2 J16 L4 Q1 Q4 R11 R12 R13 R14 R30 R49 R50 R51 R76 R78 R79 R80 R81 TP2 TP3 TP14 TP15 TP16 U5 U20
component class DLP096D_Interfaces_Sockets: D5 D6 J11 J12 J13 J14 J15 R31 R32 R75
component class DLP096D_DMD_Power: C24 C25 C27 C28 C29 C33 C34 C37 C39 C40 C69 C504 C505 C507 D4 D7 D8 L6 Q2 Q3 R17 R19 R20 R21 R33 R37 R38 R39 R40 R41 R42 R77 R503 R504 TP8 TP9 TP10 TP11 TP12 U9 U14 U22 U23
component class DLP096D_DMD_Interface: C41 C42 C49 C50 C52 C53 C55 C56 C57 C58 C59 C60 C61 C62 C63 C64 C71 C72 J9 R34 R35 R43 R44 R45 R65 R66 R69 R72 R82 R83 R84 R85 R86 R532 TP13 TP18 TP19 TP20 TP21 U13 U16 U19 U21
component class "Mounting Holes": H1 H2 H3 H4
component class Logo: Logo2
component class DLP096D_Hardware: FID1 FID2 FID3 FID4 FID5 FID6 H1 H2 H3 H4 H500 H501 H502 H503 LBL1 Logo1 Logo2 Logo3 Logo4 SH-J1 SH-J2 SH-J3 SH-J4 SH-J5 SH-J6 SH-J7 SH-J8 ZZ1 ZZ2 ZZ3 ZZ4 ZZ5
component class FiducialMark: FID1 FID2 FID3 FID4 FID5 FID6
component class AssemblyNote: ZZ1 ZZ2 ZZ3 ZZ4 ZZ5
component class Label: LBL1

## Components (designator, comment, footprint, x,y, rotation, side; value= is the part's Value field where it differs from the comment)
C1 "GCM188L81H104KA57D" FP-GCM188L81H104KA57D_0603-MFG 720.31,2836.22 r180 top locked
C2 "06035A560FAT2A" 0603 964.68,2591.79 r180 top locked value=56pF
C3 "GRM1885C1H122JA01D" 0603 997.4,2467.8 r90 top locked value=1200pF
C4 "GCJ32DL8EL225KA07L" FP-GCJ32DL8EL225KA07L_1210-MFG 653.54,2246.52 r90 top locked
C5 "GCJ32DL8EL225KA07L" FP-GCJ32DL8EL225KA07L_1210-MFG 796.05,2246.52 r90 top locked
C6 "GCM155R71H391KA37D" 0402 1744.21,2297.32 r180 top locked value=390pF
C7 "C0402C104K8RACTU" 0402 1883.02,2297.27 r0 top locked value=0.1uF
C8 "CGA2B2C0G1H151J050BA" 0402 2488.55,2297.27 r180 top locked value=150pF
C9 "C0402C104K8RACTU" 0402 2616.86,2297.27 r0 top locked value=0.1uF
C10 "GRM155R60J475ME47J" 0402 3166.6,2264.16 r270 top locked value=4.7uF
C11 "GRM186R60J226ME15D" 0603 2843.88,2276.16 r0 top locked value=22uF
C12 "GRM186R60J226ME15D" 0603 3396.16,2223.7 r90 top locked value=22uF
C13 "CC0805ZKY5V6BB106" 0805_HV 2616.86,2217.29 r0 top locked value=10uF
C14 "CC0805ZKY5V6BB106" 0805_HV 1883.02,2217.29 r0 top locked value=10uF
C15 "UCL1A331MNL1GS" CL_800x1000 1103.6,1983.5 r270 top value=330uF
C16 "UUD1A221MCL1GS" SM_RADIAL_6.3BMM 2159.24,2349.07 r0 top value=220uF
C17 "GRM033R61A104KE84D" 0201_033#1 4020.99,1898.95 r90 top locked value=0.1uF
C18 "CGA3E1X7R1C105K080AC" 0603 4033.36,1788.02 r270 top locked value=1uF
C19 "C1608X5R1V475K080AC" 0603 3681.26,1749.17 r0 top locked value=4.7uF
C20 "GRT155R71A474KE01D" 0402L 3401.06,1637.65 r0 top value=0.1uF
C21 "C1608C0G2A471J" 0603 3919.75,1682.72 r0 top locked value=470pF
C22 "C1608X5R1V475K080AC" 0603 3681.26,1678.72 r0 top locked value=4.7uF
C23 "C1608X5R1V475K080AC" 0603 3681.26,1608.27 r0 top locked value=4.7uF
C24 "C2012X5R1V106K085AC" 0805_HV 4578.59,1569.44 r0 top locked value=10uF
C25 "GRM188R6YA225KA12D" 0603 4115.92,1517.21 r270 top value=2.2uF
C26 "C0402C104K8RACTU" 0402 1768.18,1464.17 r180 top locked value=0.1uF
C27 "GCM188R71E104KA57D" 0603L 3989.06,1437.45 r180 top locked value=0.22uF
C28 "GCM188R71E104KA57D" 0603L 3785.37,1431.09 r0 top locked value=0.22uF
C29 "GRM155R71H221KA01D" 0402 4574.23,1413.83 r0 top locked value=220pF
C30 "C1608X5R1E335K080AC" 0603 2612.64,1361.99 r90 top locked value=3.3uF
C31 "C1608X5R1E335K080AC" 0603 2682.04,1361.99 r90 top locked value=3.3uF
C32 "C1608X5R1E335K080AC" 0603 2751.51,1361.99 r90 top locked value=3.3uF
C33 "GCM188R71E104KA57D" 0603L 3989.06,1375.08 r180 top locked value=0.22uF
C34 "GCM188R71E105KA64D" 0603L 3989.06,1306.09 r0 top locked value=1uF
C35 "GRM033R61A104KE84D" 0201_033#2 2153.06,1256.14 r0 top locked value=0.1uF
C36 "GRM033R61A104KE84D" 0201_033#1 2153.06,1214.65 r0 top locked value=0.1uF
C37 "GCM188R71E105KA64D" 0603L 3989.06,1252.85 r180 top locked value=1uF
C38 "C1608X5R1V475K080AC" 0603 2171.57,1307.14 r0 top locked value=4.7uF
C39 "CGA5L1X7S1A226M160AC" 1206_190L 4574.56,1049.8 r180 top value=22µF
C40 "CGA2B2X7R1H682K050BA" 0402 3921.89,1203.72 r0 top locked value=6800pF
C41 "GCM155L81E104KE02D" 0402 3419.86,1129.49 r0 top locked value=0.1uF
C42 "GCM155L81E104KE02D" 0402 3528.59,1129.49 r180 top locked value=0.1uF
C43 "C1608X5R1E335K080AC" 0603 2225.45,1110.68 r180 top locked value=3.3uF
C44 "C1608X5R1E335K080AC" 0603 2225.45,1031.22 r180 top locked value=3.3uF
C45 "C1608X5R1E335K080AC" 0603 2225.44,951.75 r180 top locked value=3.3uF
C46 "C1608X5R1E335K080AC" 0603 2233.2,835.83 r180 top locked value=3.3uF
C47 "C1608X5R1E335K080AC" 0603 2110.99,767.4 r90 top locked value=3.3uF
C48 "GRM033R61A104KE84D" 0201_033#1 2167.41,768.01 r90 top locked value=0.1uF
C49 "GCM155L81E104KE02D" 0402 3419.86,714.84 r0 top locked value=0.1uF
C50 "GCM155L81E104KE02D" 0402 3528.59,714.84 r180 top locked value=0.1uF
C51 "GRM186R60J226ME15D" 0603 557.38,638.09 r180 top locked value=22uF
C52 "GRM188R71A225KE15J" 0603L 4217.51,575.03 r90 top locked value=2.2uF
C53 "GRM188R71A225KE15J" 0603L 4217.51,458.58 r270 top locked value=2.2uF
C54 "C1608X5R1V475K080AC" 0603 2273.16,439.22 r180 top locked value=4.7uF
C55 "GCM155R71A104KA55D" 0402L 3767.94,418.38 r270 top locked value=0.1uF
C56 "GCM155L81E104KE02D" 0402 3555.92,301.28 r0 top locked value=0.1uF
C57 "GCM155L81E104KE02D" 0402 3555.92,246.28 r180 top locked value=0.1uF
C58 "GRM188R71A225KE15J" 0603L 4243.3,163.04 r0 top locked value=2.2uF
C59 "GCM188R71E104KA57D" 0603L 3734.48,162.48 r180 top locked value=0.22uF
C60 "GCM155R71A104KA55D" 0402L 4231.49,103.18 r0 top locked value=0.1uF
C61 "GCM155R71A104KA55D" 0402L 3746.29,101.36 r180 top locked value=0.1uF
C62 "GCM155R71A104KA55D" 0402L 3746.29,55.38 r180 top locked value=0.1uF
C63 "GCM188R71E104KA57D" 0603L 4243.3,44.37 r0 top locked value=0.22uF
C64 "GCM188R71E104KA57D" 0603L 3734.48,-1.74 r180 top locked value=0.22uF
C65 "C0402C104K8RACTU" 0402L 3492.43,1625.2 r180 top value=0.1uF
C66 "GRT155R71A474KE01D" 0402L 3326.3,1612.63 r90 top value=0.1uF
C68 "GRT155R71A474KE01D" 0402L 3326.3,1526.75 r270 top value=0.1uF
C69 "C0402C104K8RACTU" 0402 1855.03,1912.3 r180 top value=0.1uF
C70 "GCM188R71E104KA57D" 0603L 3959.09,2384.61 r180 top value=0.22uF
C71 "GCM155L81E104KE02D" 0402 4507.54,533.99 r0 top value=0.1uF
C72 "GRM1555C1H121FA01D" 0402 4367.32,435.17 r270 top value=120pF
C501 "C0402C104K8RACTU" 0402 1846.89,1641.21 r180 bottom locked value=0.1uF
C503 "C0402C104K8RACTU" 0402 1462.92,1410.39 r90 bottom locked value=0.1uF
C504 "GCM188R71E105KA64D" 0603L 3878.72,1353.58 r90 bottom locked value=1uF
C505 "CGA3E3X7R1H224K080AB" 0603L 3989.06,1281.53 r180 bottom locked value=0.22uF
C506 "C0402C104K8RACTU" 0402 1490.93,1235.97 r90 bottom locked value=0.1uF
C507 "C0402C104K8RACTU" 0402 4145.06,1085.17 r180 bottom locked value=0.1uF
C508 "GRM033R61A104KE84D" 0201_033#1 2858.14,1074.92 r0 bottom value=0.1uF
C509 "GRM033R61A104KE84D" 0201_033#1 2773.3,1052.42 r180 bottom locked value=0.1uF
C510 "GRM033R61A104KE84D" 0201_033#1 2691.81,1036.67 r270 bottom locked value=0.1uF
C511 "GRM033R61A104KE84D" 0201_033#1 2660.31,1036.67 r270 bottom locked value=0.1uF
C512 "GRM033R61A104KE84D" 0201_033#1 2628.82,1036.67 r270 bottom locked value=0.1uF
C513 "C1608X5R1E335K080AC" 0603 2225.44,1031.22 r180 bottom locked value=3.3uF
C514 "GRM033R61A104KE84D" 0201_033#1 2928.03,1020.92 r180 bottom locked value=0.1uF
C515 "GRM033R61A104KE84D" 0201_033#1 2833.54,1020.92 r0 bottom locked value=0.1uF
C516 "GRM033R61A104KE84D" 0201_033#1 2833.54,989.43 r0 bottom locked value=0.1uF
C517 "GRM033R61A104KE84D" 0201_033#1 2912.28,973.68 r90 bottom locked value=0.1uF
C518 "GRM033R61A104KE84D" 0201_033#1 2723.3,973.68 r270 bottom locked value=0.1uF
C519 "GRM033R61A104KE84D" 0201_033#1 2597.32,973.68 r90 bottom locked value=0.1uF
C520 "GRM033R61A104KE84D" 0201_033#1 2760.38,972.52 r270 bottom locked value=0.1uF
C521 "C1608X5R1E335K080AC" 0603 2225.44,951.75 r180 bottom locked value=3.3uF
C522 "GRM033R61A104KE84D" 0201_033#1 2865.04,957.93 r180 bottom locked value=0.1uF
C523 "GRM033R61A104KE84D" 0201_033#1 2628.82,942.18 r270 bottom locked value=0.1uF
C524 "GRM033R61A104KE84D" 0201_033#1 2565.82,939.43 r90 bottom locked value=0.1uF
C525 "GRM033R61A104KE84D" 0201_033#1 2534.33,939.43 r90 bottom locked value=0.1uF
C526 "CGA3E1X7R1C105K080AC" 0603 1548.2,898.21 r0 bottom locked value=1uF
C527 "GRM033R61A104KE84D" 0201_033#1 2896.53,894.94 r180 bottom locked value=0.1uF
C528 "GRM033R61A104KE84D" 0201_033#1 2628.82,863.44 r90 bottom locked value=0.1uF
C529 "GRM033R61A104KE84D" 0201_033#1 2597.1,863.44 r90 bottom locked value=0.1uF
C530 "GRM033R61A104KE84D" 0201_033#2 2990.77,863.44 r0 bottom locked value=0.1uF
C531 "GRM033R61A104KE84D" 0201_033#1 2930.79,863.44 r180 bottom locked value=0.1uF
C532 "GRM033R61A104KE84D" 0201_033#1 2865.04,831.95 r180 bottom locked value=0.1uF
C533 "GRM033R61A104KE84D" 0201_033#2 1609.49,795.59 r270 bottom locked value=0.1uF
C534 "GRM033R61A104KE84D" 0201_033#2 1454.77,795.59 r270 bottom locked value=0.1uF
C535 "GRM033R61A104KE84D" 0201_033#1 2928.09,802.45 r180 bottom locked value=0.1uF
C536 "GRM033R61A104KE84D" 0201_033#1 2581.52,800.45 r0 bottom locked value=0.1uF
C537 "GRM033R61A104KE84D" 0201_033#1 2943.78,753.21 r90 bottom locked value=0.1uF
C538 "GRM033R61A104KE84D" 0201_033#1 2912.28,753.21 r90 bottom locked value=0.1uF
C539 "GRM033R61A104KE84D" 0201_033#1 2880.79,753.21 r90 bottom locked value=0.1uF
C540 "GRM033R61A104KE84D" 0201_033#1 2628.82,753.21 r90 bottom locked value=0.1uF
C541 "GRM033R61A104KE84D" 0201_033#1 2597.32,753.21 r90 bottom locked value=0.1uF
C542 "GRM033R61A104KE84D" 0201_033#1 2707.5,737.46 r180 bottom locked value=0.1uF
C543 "GRM033R61A104KE84D" 0201_033#1 2817.79,720.91 r90 bottom locked value=0.1uF
C544 "C1608X5R1V475K080AC" 0603 1549.31,699.84 r180 bottom locked value=4.7uF
C545 "GRM033R61A104KE84D" 0201_033#2 2531.55,711.16 r180 bottom locked value=0.1uF
C546 "GRM033R61A104KE84D" 0201_033#1 2644.56,705.96 r180 bottom locked value=0.1uF
C547 "GRM033R61A104KE84D" 0201_033#1 2729.62,690.21 r90 bottom locked value=0.1uF
C548 "GRM033R61A104KE84D" 0201_033#1 2691.81,690.21 r90 bottom locked value=0.1uF
C549 "GRM033R61A104KE84D" 0201_033#1 2786.3,688.25 r90 bottom locked value=0.1uF
C550 "GRM033R61A104KE84D" 0201_033#1 2930.79,674.47 r180 bottom locked value=0.1uF
C551 "GRM033R61A104KE84D" 0201_033#1 2833.84,674.47 r0 bottom locked value=0.1uF
C552 "GRM033R61A104KE84D" 0201_033#1 2613.07,674.47 r180 bottom locked value=0.1uF
C553 "GRM033R61A104KE84D" 0201_033#1 2550.08,674.47 r180 bottom locked value=0.1uF
C554 "C1608X5R1E335K080AC" 0603 2459.34,622.93 r180 bottom locked value=3.3uF
C555 "C0402C104K8RACTU" 0402 608.54,506.88 r90 bottom locked value=0.1uF
C556 "C0402C104K8RACTU" 0402 518.85,255.67 r180 bottom value=0.1uF
C557 "C0402C104K8RACTU" 0402 664.56,255.67 r180 bottom value=0.1uF
D1 "B0530WSQ-13-F" SOD-323#1 4554.96,2377.62 r270 top value=30V
D2 "LSL29K-G1H2-1-Z" FP-LSL29K-G1H2-1-Z_0603-0 533.34,2181.78 r90 top locked
D3 "ZHCS2000TA" SOT-26 3944.95,2035.68 r270 top locked value=40V
D4 "SL02-M-18" DO-219AB 4439.89,1337.58 r270 top locked value=20V
D5 "LSL29K-G1H2-1-Z" FP-LSL29K-G1H2-1-Z_0603-0 2833.82,1341.6 r270 top locked
D6 "LSL29K-G1H2-1-Z" FP-LSL29K-G1H2-1-Z_0603-0 2911.38,1341.6 r270 top locked
D7 "BAT54XYH" FP-BAT54XYH_SOT363-IPC_C 3792.32,1351.61 r180 top locked value=30V
D8 "SZMM3Z3V3ST1G" SOD-323#2 4328.3,1046.98 r0 top locked value=3.3V
D9 "B0530WSQ-13-F" SOD-323#1 4483.21,2334.41 r270 top value=30V
D10 "B0530WSQ-13-F" SOD-323#1 4412.25,2289.61 r270 top value=30V
D500 "B540CQ-13-F" SMC 525.5,2627.29 r270 bottom locked value=40V
D501 "B0530WSQ-13-F" SOD-323#1 4110.9,1830.09 r270 bottom locked value=30V
FB2 "BLM18EG121SN1D" FP-BLM18EG121SN1D_0603-MFG 2278.08,513.33 r180 top locked
FID1 "Fiducial" Fiducial10-20 4235.33,2722.07 r0 top locked
FID2 "Fiducial" Fiducial10-20 280.77,0 r0 top locked
FID3 "Fiducial" Fiducial10-20 280.79,2856.95 r0 top locked
FID4 "Fiducial" Fiducial10-20 280.79,2856.95 r180 bottom locked
FID5 "Fiducial" Fiducial10-20 280.77,0 r180 bottom locked
FID6 "Fiducial" Fiducial10-20 4235.33,2722.07 r180 bottom locked
H1 "NY PMS 440 0025 PH" "NY PMS 440 0025 PH" 0,2737.45 r0 top locked
H2 "NY PMS 440 0025 PH" "NY PMS 440 0025 PH" 4528,2737.45 r0 top locked
H3 "NY PMS 440 0025 PH" "NY PMS 440 0025 PH" 0,0 r0 top locked
H4 "NY PMS 440 0025 PH" "NY PMS 440 0025 PH" 4528,0 r0 top locked
H500 "1902C" Keystone_1902C 4528,2737.45 r180 bottom locked
H501 "1902C" Keystone_1902C 0,2737.45 r180 bottom locked
H502 "1902C" Keystone_1902C 4528,0 r180 bottom locked
H503 "1902C" Keystone_1902C 0,0 r180 bottom locked
J1 "EJ508A" Memory_EJ508A 221.88,2236.18 r270 top
J2 "2005280060" FP-2005280060_CONN_11MM2_5MM25-MFG 4552.12,2259.36 r270 bottom
J3 "22284033" Molex_0022284033 2751.54,1984.78 r180 top locked
J4 "22284033" Molex_0022284033 3296.54,1984.78 r180 top locked
J5 "22284033" Molex_0022284033 2156.54,1978.66 r0 top locked
J6 "22284033" Molex_0022284033 1611.54,1978.66 r0 top locked
J7 "571-0500" 571-0500 182.7,1723.5 r0 top locked
J8 "571-0100" 571-0100 182.7,973.5 r0 top locked
J9 "DMD Interposer" FP-2516672_SMD_CONN_LGA-56-MFG 3988.89,308.14 r90 top locked
J10 "TSM-104-01-L-DV" Samtec_TSM-104-01-x-DV 143.27,410.2 r180 top locked
J11 "702461002" FP-702461002_HDR10-MFG 1413.4,1.24 r180 top
J12 "FTR-110-03-G-D-06" FP-FTR-110-03-G-D-06_HDR19-MFG 640.94,-0.09 r0 top locked
J13 "RSM-110-02-L-D" Samtec_RSM-110-02-x-D 3307.19,-0.09 r180 top locked
J14 "FLE-108-01-G-DV-A" Samtec_FLE-108-01-x-DV-A 2106.28,-0.09 r180 top locked
J15 "FLE-108-01-G-DV-A" Samtec_FLE-108-01-x-DV-A 2689.59,-0.09 r180 top locked
J16 "TSW-104-07-G-S" TSW-104-07-G-S 4646.25,2257.62 r270 top
L1 "MSS1210-153ME" MSS1210 1304.76,2584.22 r270 top locked value=15uH
L2 "XAL5030-222MEB" XAL5030 1860.38,2612.48 r0 top value=2.2uH
L3 "XAL5030-222MEB" XAL5030 2812.21,2463.89 r270 top locked value=2.2uH
L4 "SRN5040TA-220M" SRN5040TA 4030.55,2247.8 r90 top locked value=22uH
L5 "MLP2012V2R2MT0S1" 0805_HV 3309.74,2230.94 r270 top locked value=2.2uH
L6 "FDSD0420D-4R7M" FDSD0420 4597.78,1245.02 r90 top locked value=4.7uH
LBL1 "THT-14-423-10" Label_650x200 3524.72,2481.66 r0 top
Logo1 "FCC disclaimer" FCC_disclaimer 3087.81,2840.05 r0 top locked
Logo2 "Texas Instruments" TI_Stacked_Overlay_Small 3221,2717.56 r0 top
Logo3 "WEEE logo" WEEE_Minimum 938.51,935.59 r0 top locked
Logo4 "CE Mark" CE_Mark_5mm 940.47,460.2 r0 top locked
Q1 "DMT3020LFDB-13" U-DFN2020-6_B 4306.7,2423.91 r0 top value=30V
Q2 "NX3008NBKS,115" FP-NX3008NBKS,115_TSSOP6-IPC_C 4339.62,946.48 r180 top locked
Q3 "NX3008CBKS,115" SOT-363 4500.66,920.89 r180 top locked value=-30V
Q4 "DMT3020LFDB-13" U-DFN2020-6_B 4307.78,2257.18 r0 top value=30V
R1 "CRCW0603158KFKEA" 0603 997.4,2715.77 r270 top locked value=158k
R2 "CRCW0603100KFKEA" 0603 923.09,2467.8 r270 top locked value=100k
R3 "CR0603-FX-3163ELF" FP-CR0603-FX-3163ELF_0603-MFG 965.9,2355.36 r0 top locked value=316k
R4 "CRCW04021K80JNED" 0402L 534.88,2291.76 r90 top locked value=1.8k
R5 "ERJ-6ENF1003V" 0805_HV 2018.69,2575.74 r270 top value=100k
R6 "RC0603FR-07180KL" 0603 2095.46,2711.22 r270 top value=180k
R7 "RC0603FR-0775KL" 0603 2843.88,2184.26 r180 top locked value=75.0k
R8 "RC0603FR-07150KL" 0603 2992.09,2184.26 r180 top locked value=150k
R9 "RC0603FR-07562KL" 0603 2095.46,2561.62 r270 top value=562k
R10 "ERJ-6ENF1003V" 0805_HV 2616.86,2112.99 r180 top locked value=100k
R11 "MCR25JZHFLR110" 1210 3649.76,1888.94 r270 top locked value=0.11
R12 "RC0603FR-078K2L" 0603 3919.75,1747.63 r180 top locked value=8.20k
R13 "CRCW04021K80JNED" 0402L 3401.06,1679.17 r180 top value=1.8k
R14 "CRCW04023K00JNED" 0402L 3401.06,1720.69 r180 top value=3.0k
R15 "ERJ-8ENF3481V" 1206 1504.74,1583.01 r180 top locked value=3.48k
R16 "MCR01MZPJ000" 0402 2030.72,1517.32 r270 top locked value=0
R17 "ERA-2AEB822X" FP-ERA-2AEB822X_0402-IPC_C 4340.33,1515.27 r270 top locked
R18 "RC0201JR-0710KL" 0201#1 2085.41,1506.97 r270 top locked value=10k
R19 "ERA-2AEB104X" FP-ERA-2AEB104X_0402-IPC_C 4262.27,1500.46 r180 top locked
R20 "ERA-2AEB104X" FP-ERA-2AEB104X_0402-IPC_C 4565.36,1482.23 r180 top locked
R21 "TNPW040215K6BEED" FP-TNPW040215K6BEED_0402-IPC_C 4646.06,1482.23 r180 top locked
R22 "ERJ-6ENF1003V" 0805_HV 1585.77,1434.9 r270 top locked value=100k
R23 "RC0201JR-0710KL" 0201#1 2519.82,1493.21 r0 top locked value=10k
R24 "ERJ-6ENF6651V" 0805_HV 1360.62,1428.49 r270 top locked value=6.65k
R25 "RC0201JR-0710KL" 0201#1 2078.92,1418.98 r270 top locked value=10k
R26 "RC0201JR-0710KL" 0201#1 2519.82,1393.21 r0 top locked value=10k
R27 "CRCW080510K2FKEA" 0805_HV 1383.27,1237.49 r270 top locked value=10.2k
R28 "ERJ-6ENF1003V" 0805_HV 1585.77,1226.64 r270 top locked value=100k
R29 "RC0201JR-0710KL" 0201#1 2631.07,1248.38 r90 top locked value=10k
R30 "CRCW04023K00JNED" 0402L 3240.8,1613.07 r270 top value=3.0k
R31 "CRCW04021K80JNED" 0402L 2833.82,1236.74 r270 top locked value=1.8k
R32 "CRCW04021K80JNED" 0402L 2911.38,1236.74 r270 top locked value=1.8k
R33 "CRCW04026K81FKED" 0402 4024.88,1203.72 r0 top locked value=6.81k
R34 "CRCW060310K0JNEA" 0603 3319.63,1137.51 r270 top locked value=10k
R35 "CRCW060310K0JNEA" 0603 3617.77,1137.51 r270 top locked value=10k
R36 "RC0603FR-074K32L" 0603 1351.77,1115.55 r180 top locked value=4.32k
R37 "ERJ-2GEJ102X" 0402L 4141.12,1085.17 r180 top locked value=1.0k
R38 "CRCW040213R0JNED" 0402L 4416.95,991.75 r90 top locked value=13
R39 "ERJ-2GEJ102X" 0402L 4227.71,926.79 r90 top locked value=1.0k
R40 "ERJ-2GEJ103X" 0402L 4599.09,946.48 r180 top locked value=10k
R41 "CRCW040239R0JNED" 0402L 4599.09,895.3 r180 top locked value=39
R42 "CRCW040239R0JNED" 0402L 4328.73,860.32 r0 top locked value=39
R43 "CRCW060310K0JNEA" 0603 3413.6,820.04 r180 top locked value=10k
R44 "CRCW060310K0JNEA" 0603 3319.63,720.01 r270 top locked value=10k
R45 "CRCW060310K0JNEA" 0603 3617.77,720.01 r270 top locked value=10k
R46 "ERJ-3EKF49R9V" 0603 716.35,638.09 r0 top locked value=49.9
R47 "RC0201JR-0710KL" 0201#1 365.13,560.2 r0 top locked value=10k
R48 "ERJ-2GEJ102X" 0402L -82.21,560.2 r0 top locked value=1.0k
R49 "CRCW04021K80JNED" 0402L 3283.55,1612.6 r270 top value=1.8k
R50 "CRCW04023K00JNED" 0402L 3240.8,1526.57 r90 top value=3.0k
R51 "CRCW04021K80JNED" 0402L 3283.55,1526.76 r90 top value=1.8k
R62 "CRCW04022K32FKED" 0402 2386.96,441.29 r90 top locked value=2.32k
R63 "RC0201JR-0710KL" 0201#1 365.13,460.2 r0 top locked value=10k
R64 "ERJ-2GEJ102X" 0402L -82.21,460.2 r0 top locked value=1.0k
R65 "RC0201JR-0710KL" 0201#1 3729.21,418.38 r90 top locked value=10k
R66 "CRCW060310K0JNEA" 0603 3408.6,402.55 r180 top locked value=10k
R67 "RC0201JR-0710KL" 0201#1 365.13,360.2 r0 top locked value=10k
R68 "ERJ-2GEJ102X" 0402L -82.21,360.98 r0 top locked value=1.0k
R69 "CRCW060310K0JNEA" 0603 3321.32,307.91 r0 top locked value=10k
R70 "RC0201JR-0710KL" 0201#1 365.13,260.2 r0 top locked value=10k
R71 "ERJ-2GEJ102X" 0402L -82.21,259.03 r0 top locked value=1.0k
R72 "CRCW060310K0JNEA" 0603 3321.32,239.44 r0 top locked value=10k
R73 "CRCW040210K0FKED" 0402 728.24,575.8 r180 top value=10.0k
R74 "RMCF0805ZT0R00" FP-RMCF0805ZT0R00_0805-IPC_C 2242.29,754.57 r0 top
R75 "ERJ-2GEJ101X" 0402L 355.48,132.96 r270 top value=100
R76 "MCR01MZPJ000" 0402 3815.8,1672.98 r270 top value=0
R77 "ERJ-2GEJ103X" 0402L 1947.17,1911 r0 top value=10k
R78 "ERJ-2GEJ101X" 0402L 4143.06,2020.99 r90 top value=100
R79 "ERJ-2GEJ101X" 0402L 4192.79,2020.43 r90 top value=100
R80 "ERJ-2GEJ101X" 0402L 4292.24,2020.01 r90 top value=100
R81 "ERJ-2GEJ101X" 0402L 4242.51,2020.43 r90 top value=100
R82 "RC0201JR-0710KL" 0201#1 4218.3,690.49 r90 top value=10k
R83 "RC0603FR-0756RL" 0603 4326.16,521.14 r180 top value=56.0
R84 "RC0603FR-0756RL" 0603 4308.7,423.51 r270 top value=56.0
R85 "RC0201JR-0710KL" 0201#1 4624.63,539.81 r90 top value=10k
R86 "RC0201JR-0710KL" 0201#1 4588.16,539.69 r90 top value=10k
R500 "CRCW040241K2FKED" 0402 844.28,2532.12 r270 bottom locked value=41.2k
R503 "ERA-2AEB1212X" FP-ERA-2AEB1212X_0402-MFG 4115.92,1240.09 r270 bottom locked
R504 "ERA-2AEB104X" FP-ERA-2AEB104X_0402-MFG 4069.89,1164.01 r270 bottom locked
R505 "RC0201JR-0710KL" 0201#2 1511.83,601.17 r90 bottom locked value=10k
R519 "CRCW040210K0FKED" 0402 2386.96,441.29 r270 bottom locked value=10.0k
R520 "MCR01MZPJ000" 0402 1507.89,434.77 r0 bottom locked value=0
R532 "CRCW060310K0JNEA" 0603 3486.11,379.12 r180 bottom locked value=10k
SH-J1 "M7582-05" Harwin_M7582-05 2801.54,1984.78 r0 top locked
SH-J2 "M7582-05" Harwin_M7582-05 3346.54,1984.78 r0 top locked
SH-J3 "M7582-05" Harwin_M7582-05 2106.54,1978.66 r0 top locked
SH-J4 "M7582-05" Harwin_M7582-05 1561.54,1978.66 r0 top locked
SH-J5 "M7582-05" Harwin_M7582-05 143.27,260.19 r0 top locked
SH-J6 "M7582-05" Harwin_M7582-05 143.27,460.2 r0 top locked
SH-J7 "M7582-05" Harwin_M7582-05 143.27,560.2 r0 top locked
SH-J8 "M7582-05" Harwin_M7582-05 143.27,360.2 r0 top locked
TP1 "5001" Keystone5001 329.46,2634 r90 top locked
TP2 "TP_H0.45P0.75" TP_H045P075 4143.43,2089.2 r90 top
TP3 "TP_H0.45P0.75" TP_H045P075 4197.91,2089.2 r90 top
TP4 "5001" Keystone5001 1611.54,2196.14 r90 top locked
TP5 "5001" Keystone5001 2424.51,2112.99 r90 top locked
TP6 "5001" Keystone5001 2751.54,1781.7 r90 top locked
TP7 "5001" Keystone5001 3297.24,1781.7 r90 top locked
TP8 "5001" Keystone5001 4247.21,1690.54 r90 top
TP9 "5001" Keystone5001 4548.08,1690.54 r270 top locked
TP10 "5001" Keystone5001 3644.55,1399.54 r90 top
TP11 "5001" Keystone5001 3908.42,983.88 r270 top locked
TP12 "5001" Keystone5001 4501.69,704.62 r180 top locked
TP13 "TP_H0.45P0.75" TP_H045P075 4281.77,264.5 r180 top
TP14 "TP_H0.45P0.75" TP_H045P075 4306.86,2087.97 r0 top
TP15 "TP_H0.45P0.75" TP_H045P075 4252.38,2087.15 r0 top
TP16 "TP_H0.45P0.75" TP_H045P075 3801.12,1750.42 r0 top
TP17 "5001" Keystone5001 913.66,1332.98 r90 top
TP18 "TP_H0.45P0.75" TP_H045P075 4389.08,184.84 r90 top
TP19 "TP_H0.45P0.75" TP_H045P075 4389.08,277.09 r90 top
TP20 "TP_H0.45P0.75" TP_H045P075 4389.08,323.21 r90 top
TP21 "TP_H0.45P0.75" TP_H045P075 4389.08,230.96 r90 top
TP22 "TP_H0.45P0.75" TP_H045P075 2418.88,514.41 r90 top
TP23 "DAC_OUT" TP_H045P075 2640.68,516.52 r90 top
U1 "LM5013QDDARQ1" DDA0008E-MFG 769.28,2621.68 r90 top
U2 "TPS62130AQRGTTQ1" RGT0016C 1849.56,2409.85 r270 top locked
U3 "TPS62130AQRGTTQ1" RGT0016C 2590.39,2409.85 r270 top locked
U4 "LM3671TLX-1.8/NOPB" YZR0005AEBA 3229.8,2270.72 r0 top locked
U5 "TPS92515QDGQRQ1" DGQ0010E_N 3862.94,1866.11 r180 top locked
U6 "SN74LVC2G08IDCTRQ1" DCT0008A_N 1792.76,1602.82 r0 top locked
U7 "S25FL128SAGNFV003" FP-S25FL128SAGNFI000_WSON8-MFG 2292.46,1468.98 r180 top locked
U8 "TPS389001QDSERQ1" DSE0006A 1472.07,1448.8 r0 top locked
U9 "TPS65100QPWPRQ1" PWP0024B_NV_L 4228.13,1293.29 r180 top locked
U10 "SN74AHC1G32TDBVRQ1" DBV0005A_N 1768.18,1352.07 r0 top locked
U11 "TPS3703E4080DSERQ1" DSE0006A 1490.93,1243.72 r90 top locked
U12 "XAM2634AOLFGMZCZQ" ZCZ0324A-MFG 2754.8,863.44 r0 top locked
U13 "SN74AXC8T245RHLR" RHL0024A 3447.07,977.29 r0 top locked
U14 "SN74AHC1G04QDBVRQ1" DBV0005A_N 4114.78,983.88 r0 top locked
U15 "MTFC8GAMALNA-AAT" FP-MTFC128GAPALNA-AAT_TBGA100-MFG 1511.83,694.3 r0 top locked
U16 "SN74AXC8T245RHLR" RHL0024A 3447.07,559.8 r0 top locked
U17 "SN74LVC1G14QDCKRQ1" DCK0005A_N 588.87,527.54 r270 top locked
U18 "TXU0104BQAR" BQA0014A-MFG 587.58,351.41 r180 top locked
U19 "SN74AXC2T245RSW" RSW0010A 3447.11,273.55 r0 top locked
U20 "TS5A3357QDCURQ1" DCU0008A_N 3452.42,1550.68 r0 top
U21 "TMP411AQDGKRQ1" DGK0008A_N 4517.24,437.66 r0 top
U22 "TPS3840DL47DBVRQ1" DBV0005A_N 1875.94,1804.15 r270 top
U23 "TPS22919DCKT" DCK0006A_N 4445.29,1142.49 r90 top
Y1 "ECS-2520S18-250-FN-TR" ECS_ECS-2520S 2301.82,630.17 r90 top locked
ZZ1 "This Assembly Note is for PCB labels only" AssemblyNoteLabel -91.1,3493.61 r0 top locked
ZZ2 "These assemblies are ESD sensitive, ESD precautions shall be observed." AssemblyNote -91.1,3384.72 r0 top locked
ZZ3 "These assemblies must be clean and free from flux and all contaminants. Use of no clean flux is not acceptable." AssemblyNote -91.1,3296.17 r0 top locked
ZZ4 "These assemblies must comply with workmanship standards IPC-A-610 Class 2, unless otherwise specified." AssemblyNote -91.1,3207.61 r0 top locked
ZZ5 "Indication provided for the D* components at their cathode side." AssemblyNote -91.29,3108.68 r0 top locked

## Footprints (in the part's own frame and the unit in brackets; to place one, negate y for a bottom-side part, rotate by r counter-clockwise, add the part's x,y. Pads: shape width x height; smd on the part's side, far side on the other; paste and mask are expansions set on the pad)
0201#1 [mm] "Data from Kemet datasheet CC101_COM dated 7/28/11"
  rect 0.46x0.42 smd mask+0.048: 1(-0.33,0) 2(0.33,0)
  body extent -0.31,-0.16 0.31,0.16, height 0.26
0201#2 [mm] "Data from Kemet datasheet CC101_COM dated 7/28/11"
  rect 0.46x0.42 smd: 1(-0.33,0) 2(0.33,0)
  body extent -0.31,-0.16 0.31,0.16, height 0.26
0201_033#1 [mm] "SMD, 2-Leads, Height 0.33mm"
  rect 0.46x0.42 smd mask+0.048: 1(-0.33,0) 2(0.33,0)
  body extent -0.31,-0.16 0.31,0.16, height 0.33
0201_033#2 [mm] "SMD, 2-Leads, Height 0.33mm"
  rect 0.46x0.42 smd: 1(-0.33,0) 2(0.33,0)
  body extent -0.31,-0.16 0.31,0.16, height 0.33
0402 [mm] "0402 from SM-752 data"
  rect 0.8x0.6 smd: 1(-0.6,0) 2(0.6,0)
  silkscreen extent -1.22,-0.52 1.22,0.52, body extent -0.55,-0.3 0.55,0.3, height 0.6
0402L [mm] "0402 from SM-752 data"
  rect 0.6x0.5 smd: 1(-0.5,0) 2(0.5,0)
  body extent -0.55,-0.3 0.55,0.3, height 0.6
571-0100 [mm] "Deltron Emcon recommended land pattern 2003-10-13"
  rect 2.3x2.3 hole 1.8: 1(-7.65,0)
  round 2.3 hole 1.8: 2(7.65,0)
  silkscreen extent -9.74,-5.47 11.09,4.88, body extent -12.28,-5.48 11.09,4.88, height 12.41
571-0500 [mm] "Deltron Emcon recommended land pattern 2003-10-13"
  rect 2.3x2.3 hole 1.8: 1(-7.65,0)
  round 2.3 hole 1.8: 2(7.65,0)
  silkscreen extent -9.74,-5.47 11.09,4.88, body extent -12.28,-5.48 11.09,4.88, height 12.41
0603 [mm] "0603 from SM-752 data"
  rect 1x0.95 smd: 1(-0.8,0) 2(0.8,0)
  silkscreen extent -1.52,-0.69 1.52,0.69, body extent -0.87,-0.47 0.87,0.47, height 1
0603L [mm] "0603 from SM-752 data"
  rect 0.8x0.85 smd: 1(-0.7,0) 2(0.7,0)
  silkscreen extent -0.07,-0.33 0.07,0.33, body extent -0.87,-0.47 0.87,0.47, height 1
0805_HV [mil] "0805 with 30mil clearance between pads"
  rect 50x63 smd: 1(-40,0) 2(40,0)
  silkscreen extent -74,-40 74,40, body extent -43,-29 43,29, height 57
1206 [mm] "1206 from SM-752 data"
  rect 1.3x1.85 smd: 1(-1.45,0) 2(1.45,0)
  silkscreen extent -2.4,-1.21 2.4,1.21, body extent -1.7,-0.9 1.7,0.9, height 1.35
1206_190L [mm] "1206_190"
  rect 1.1x1.75 smd: 1(-1.35,0) 2(1.35,0)
  silkscreen extent -0.4,-0.77 0.4,0.77, body extent -1.75,-0.95 1.75,0.95, height 1.9
1210 [mm] "1210 from SM-752 data"
  rect 1.3x2.7 smd: 1(-1.45,0) 2(1.45,0)
  silkscreen extent -2.32,-1.57 2.32,1.57, body extent -1.7,-1.35 1.7,1.35, height 1.35
AssemblyNote [mil] "Assembly Note"
AssemblyNoteLabel [mil] "Assembly Note for PCB Labels"
BQA0014A-MFG [mm]
  rrect40% 0.25x0.6 smd paste+0 mask+0: 1(-0.25,1.4) 7(-0.25,-1.4) 8(0.25,-1.4) 14(0.25,1.4)
  rrect40% 0.6x0.25 smd paste+0 mask+0: 2(-1.15,1) 3(-1.15,0.5) 4(-1.15,0) 5(-1.15,-0.5) 6(-1.15,-1) 9(1.15,-1) 10(1.15,-0.5) 11(1.15,0) 12(1.15,0.5) 13(1.15,1)
  rrect10% 1x1.5 smd paste-1000 mask+0: 15(0,0)
  silkscreen extent -1.3,-1.55 1.3,2.37, body extent -1.55,-1.8 1.55,1.8, height 0.25
CE_Mark_5mm [mil] "Minimum text height for CE Mark"
  silkscreen extent -138,-98 138,98
CL_800x1000 [mm] "SMD, 2-Leads, Dia 8mm"
  rrect4% 3.5x2.5 smd: 1(-3.25,0) 2(3.25,0)
  body extent -4.45,-4.15 4.45,4.15, height 10.5
DBV0005A_N [mm] "SOT23, 5-Leads, Body 2.9x1.6mm, Pitch 0.95mm, Lead Span 2.8mm, IPC Medium Density"
  rrect17% 1x0.6 smd: 1(-1.375,0.95) 2(-1.375,0) 3(-1.375,-0.95) 4(1.375,-0.95) 5(1.375,0.95)
  silkscreen extent -0.25,-1.55 0.25,1.55, body extent -1.42,-1.46 1.42,1.46, height 1.09
DCK0005A_N [mm] "SOT353, 5-Leads, Body 2x1.3mm, Pitch 0.65mm, Lead Span 2.1mm, IPC Medium Density"
  rrect25% 0.85x0.4 smd: 1(-1.125,0.65) 2(-1.125,0) 3(-1.125,-0.65) 4(1.125,-0.65) 5(1.125,0.65)
  silkscreen extent -1.48,-1.03 0.55,1.1, body extent -1.14,-1 1.14,1, height 0.95
DCK0006A_N [mm] "SOT23, 6-Leads, Body 2x1.3mm, Pitch 0.65mm, Lead Span 2.1mm, IPC Medium Density"
  rrect25% 0.85x0.4 smd: 1(-1.125,0.65) 2(-1.125,0) 3(-1.125,-0.65) 4(1.125,-0.65) 5(1.125,0) 6(1.125,0.65)
  silkscreen extent -1.5,-1.09 0.51,1.09, body extent -1.14,-1 1.14,1, height 0.95
DCT0008A_N [mm] "TSOP, 8-Leads, Body 3x2.8mm, Pitch 0.65mm, IPC Medium Density"
  oval 1.05x0.4 smd: 1(-1.975,0.975) 2(-1.975,0.325) 3(-1.975,-0.325) 4(-1.975,-0.975) 5(1.975,-0.975) 6(1.975,-0.325) 7(1.975,0.325) 8(1.975,0.975)
  silkscreen extent -2.32,-1.57 0.6,1.58, body extent -2.01,-1.47 2.01,1.48, height 1.3
DCU0008A_N [mm] "TSSOP, 8-Leads, Body 2x2.3mm, Pitch 0.5mm, IPC Medium Density"
  oval 0.8x0.3 smd: 1(-1.6,0.75) 2(-1.6,0.25) 3(-1.6,-0.25) 4(-1.6,-0.75) 5(1.6,-0.75) 6(1.6,-0.25) 7(1.6,0.25) 8(1.6,0.75)
  silkscreen extent -1.05,-1.05 0.38,1.05, body extent -1.56,-1 1.56,1, height 0.9
DDA0008E-MFG [mm]
  rrect20% 2.2x0.5 smd paste-1000 mask+0: 1(-2.875,1.905) 2(-2.875,0.635) 3(-2.875,-0.635) 4(-2.875,-1.905) 5(2.875,-1.905) 6(2.875,-0.635) 7(2.875,0.635) 8(2.875,1.905)
  rrect3% 2.95x4.9 smd paste-1000 mask-1000: 9(0,0)
  silkscreen extent -4.67,-2.83 2,2.83, body extent -4.08,-2.68 4.08,2.68, height 0.25
DGK0008A_N [mm] "TSOP, 8-Leads, Body 3x3mm, Pitch 0.65mm, IPC Medium Density"
  oval 1.35x0.45 smd: 1(-2.225,0.975) 2(-2.225,0.325) 3(-2.225,-0.325) 4(-2.225,-0.975) 5(2.225,-0.975) 6(2.225,-0.325) 7(2.225,0.325) 8(2.225,0.975)
  silkscreen extent -2.75,-1.55 0.95,1.55, body extent -2.45,-1.5 2.45,1.5, height 0.96
DGQ0010E_N [mm] "TSSOP, 10-Leads, Body 3x3mm, Pitch 0.5mm, Thermal Pad 1.83x2.1mm, IPC Medium Density"
  rrect100% 1.35x0.3 smd: 1(-2.225,1) 2(-2.225,0.5) 3(-2.225,0) 4(-2.225,-0.5) 5(-2.225,-1) 6(2.225,-1) 7(2.225,-0.5) 8(2.225,0) 9(2.225,0.5) 10(2.225,1)
  rrect5% 1.83x2.1 smd: 11(0,0)
  silkscreen extent -2.73,-1.55 0.9,1.55, body extent -2.46,-1.5 2.46,1.5, height 0.95
DO-219AB [mm] "Vishay Semiconductor"
  rrect8% 1.3x1.4 smd: 1(-1.45,0) 2(1.45,0)
  silkscreen extent -1.9,-1.07 1.23,1.07, body extent -1.95,-0.95 1.95,0.95, height 1.09
DSE0006A [mm] "TI recommended land pattern"
  rect 0.66x0.25 smd: 1(-0.62,0.5)
  rect 0.7x0.25 smd: 2(-0.6,0) 3(-0.6,-0.5) 4(0.6,-0.5) 5(0.6,0) 6(0.6,0.5)
  Top Layer region: -0.3,0.625 -0.25,0.625 -0.15,0.525 -0.15,0.375 -0.3,0.375
  silkscreen extent -0.9,-0.92 0.9,0.92, body extent -0.77,-0.77 0.77,0.77, height 0.8
ECS_ECS-2520S [mm] "SMD, 4-Leads, Body 2x2.5mm"
  rrect12% 0.8x0.9 smd: 1(-0.725,0.925) 2(-0.725,-0.925) 3(0.725,-0.925) 4(0.725,0.925)
  silkscreen extent -1.7,0.9 -1.5,1.1, body extent -1.05,-1.3 1.05,1.3, height 1
FCC_disclaimer [mil]
FDSD0420 [mm] "SMD, 2-Leads, Body 4.2x4.2mm"
  rect 1.4x2.4 smd: 1(-1.6,0) 2(1.6,0)
  silkscreen extent -2.2,-2.2 2.2,2.2, body extent -2.1,-2.1 2.1,2.1, height 2
Fiducial10-20 [mm]
  round 1 smd mask+0.5: 1(0,0)
  Top Layer keep-out circle w1.178: c0,0 r0.5
FP-2516672_SMD_CONN_LGA-56-MFG [mm]
  rrect13% 0.75x0.75 smd paste-1000 mask+0: A2(6.3,3) A3(5.3,3) A4(4.3,3) A5(3.3,3) A12(-3.7,3) A13(-4.7,3) A14(-5.7,3) A15(-6.7,3) B2(6.3,2) B3(5.3,2) B4(4.3,2) B5(3.3,2) B12(-3.7,2) B13(-4.7,2) B14(-5.7,2) B15(-6.7,2) C2(6.3,1) C3(5.3,1) C4(4.3,1) C5(3.3,1) C12(-3.7,1) C13(-4.7,1) C14(-5.7,1) C15(-6.7,1) D2(6.3,0) D3(5.3,0) D4(4.3,0) D5(3.3,0) D12(-3.7,0) D13(-4.7,0) D14(-5.7,0) D15(-6.7,0) E2(6.3,-1) E3(5.3,-1) E4(4.3,-1) E5(3.3,-1) E12(-3.7,-1) E13(-4.7,-1) E14(-5.7,-1) E15(-6.7,-1) F2(6.3,-2) F3(5.3,-2) F4(4.3,-2) F5(3.3,-2) F12(-3.7,-2) F13(-4.7,-2) F14(-5.7,-2) F15(-6.7,-2) G2(6.3,-3) G3(5.3,-3) G4(4.3,-3) G5(3.3,-3) G12(-3.7,-3) G13(-4.7,-3) G14(-5.7,-3) G15(-6.7,-3)
  round 2.35 hole 2.35 unplated paste-1000: ""(-11.45,-3.7) ""(-11.45,3.7) ""(11.35,-3.7) ""(11.35,3.7)
  round 2.4 hole 2.4 unplated paste-1000: ""(-9.8,0)
  rrect100% 2.95x2.4 hole 2.4 slot 2.95 at 0 deg unplated paste-1000: ""(9.55,0)
  silkscreen extent -11.86,-4.5 11.86,4.5, body extent -11.72,-4.5 11.98,4.5, height 1.4
FP-702461002_HDR10-MFG [mm]
  rrect6% 1.74x1.74 hole 1.14 paste-1000 mask+0: 1(-5.08,-1.275)
  round 1.74 hole 1.14 paste-1000 mask+0: 2(-5.08,1.265) 3(-2.54,-1.275) 4(-2.54,1.265) 5(0,-1.275) 6(0,1.265) 7(2.54,-1.275) 8(2.54,1.265) 9(5.08,-1.275) 10(5.08,1.265)
  silkscreen extent -10.26,-5.34 10.26,4.54, body extent -10.36,-4.64 10.36,4.64, height 0.25
FP-2005280060_CONN_11MM2_5MM25-MFG [mm]
  rrect25% 0.4x1 smd paste+0 mask+0: 1(-2.5,2.475) 2(-1.5,2.475) 3(-0.5,2.475) 4(0.5,2.475) 5(1.5,2.475) 6(2.5,2.475)
  rrect8% 2x1.3 smd paste+0 mask+0: 7(-5.3,-0.225) 8(5.3,-0.225)
  silkscreen extent -5.7,-2.73 5.7,3.67, body extent -6,-1.43 6,2.67, height 4.15
FP-BAT54XYH_SOT363-IPC_C [mm]
  rrect29% 0.759x0.342 smd: 1(-0.877,0.65)
  rrect100% 0.759x0.342 smd: 2(-0.877,0) 3(-0.877,-0.65) 4(0.877,-0.65) 5(0.877,0) 6(0.877,0.65)
  silkscreen extent -1.96,-1 0.12,1, body extent -1.36,-1.1 1.36,1.1, height 0.25
FP-BLM18EG121SN1D_0603-MFG [mm]
  rrect15% 0.65x0.7 smd paste+0 mask+0: 1(-0.675,0) 2(0.675,0)
  silkscreen extent -0.88,-0.8 0.88,0.8, body extent -0.8,-0.4 0.8,0.4, height 0.95
FP-CR0603-FX-3163ELF_0603-MFG [mm]
  rrect15% 0.65x0.9 smd: 1(-0.725,0) 2(0.725,0)
  silkscreen extent 0,-0.45 0,0.45, body extent -0.8,-0.4 0.8,0.4, height 0.55
FP-ERA-2AEB104X_0402-IPC_C [mil]
  rrect19% 22.03x20.31 smd: 1(-14.81,0) 2(14.81,0)
  silkscreen extent -26,-28 26,28, body extent -30,-16 30,16, height 10
FP-ERA-2AEB104X_0402-MFG [mm]
  rrect21% 0.475x0.5 smd paste+0 mask+0: 1(-0.512,0) 2(0.512,0)
  silkscreen extent -0.5,-0.63 0.5,0.63, body extent -0.5,-0.25 0.5,0.25, height 0.4
FP-ERA-2AEB822X_0402-IPC_C [mil]
  rrect19% 22.03x20.31 smd: 1(-14.81,0) 2(14.81,0)
  silkscreen extent -26,-28 26,28, body extent -30,-16 30,16, height 10
FP-ERA-2AEB1212X_0402-MFG [mm]
  rrect21% 0.475x0.5 smd paste+0 mask+0: 1(-0.512,0) 2(0.512,0)
  silkscreen extent -0.5,-0.63 0.5,0.63, body extent -0.5,-0.25 0.5,0.25, height 0.4
FP-FTR-110-03-G-D-06_HDR19-MFG [mil]
  rrect14% 28x123 smd paste+0 mask+0: 1(-225,-101.5) 2(-225,101.5) 3(-175,-101.5) 4(-175,101.5) 5(-125,-101.5) 7(-75,-101.5) 8(-75,101.5) 9(-25,-101.5) 10(-25,101.5) 11(25,-101.5) 12(25,101.5) 13(75,-101.5) 14(75,101.5) 15(125,-101.5) 16(125,101.5) 17(175,-101.5) 18(175,101.5) 19(225,-101.5) 20(225,101.5)
  silkscreen extent -266,-131 251,101, body extent -255,-167 255,167, height 10
FP-GCJ32DL8EL225KA07L_1210-MFG [mm]
  rrect9% 1.1x2.05 smd paste+0 mask+0: 1(-1.65,0) 2(1.65,0)
  silkscreen extent -1.8,-1.4 1.8,1.4, body extent -2.3,-1.5 2.3,1.5, height 0.25
FP-GCM188L81H104KA57D_0603-MFG [mm]
  rrect15% 0.65x0.7 smd paste+0 mask+0: 1(-0.675,0) 2(0.675,0)
  body extent -1.1,-0.55 1.1,0.55, height 0.25
FP-LSL29K-G1H2-1-Z_0603-0 [mm]
  rrect13% 0.8x0.8 smd paste-1000 mask+0: 1(-0.75,0) 2(0.75,0)
  silkscreen extent -1.77,-0.77 0.7,0.77, body extent -1.25,-0.55 1.25,0.55, height 0.25
FP-MTFC128GAPALNA-AAT_TBGA100-MFG [mm]
  round 0.4 smd: A1(-4.5,8) A2(-3.5,8) A9(3.5,8) A10(4.5,8) B1(-4.5,7) B10(4.5,7) D2(-3.5,5) D3(-2.5,5) D4(-1.5,5) D5(-0.5,5) D6(0.5,5) D7(1.5,5) D8(2.5,5) D9(3.5,5) E2(-3.5,4) E3(-2.5,4) E4(-1.5,4) E5(-0.5,4) E6(0.5,4) E7(1.5,4) E8(2.5,4) E9(3.5,4) F2(-3.5,3) F3(-2.5,3) F4(-1.5,3) F5(-0.5,3) F6(0.5,3) F7(1.5,3) F8(2.5,3) F9(3.5,3) G2(-3.5,2) G3(-2.5,2) G4(-1.5,2) G5(-0.5,2) G6(0.5,2) G7(1.5,2) G8(2.5,2) G9(3.5,2) H2(-3.5,1) H3(-2.5,1)
  round 0.4 smd paste+0 mask-1000: H4(-1.5,1) H5(-0.5,1) H6(0.5,1) H7(1.5,1) H8(2.5,1) H9(3.5,1) J2(-3.5,0) J3(-2.5,0) J4(-1.5,0) J5(-0.5,0) J6(0.5,0) J7(1.5,0) J8(2.5,0) J9(3.5,0) K2(-3.5,-1) K3(-2.5,-1) K4(-1.5,-1) K5(-0.5,-1) K6(0.5,-1) K7(1.5,-1) K8(2.5,-1) K9(3.5,-1) L2(-3.5,-2) L3(-2.5,-2) L4(-1.5,-2) L5(-0.5,-2) L6(0.5,-2) L7(1.5,-2) L8(2.5,-2) L9(3.5,-2) M2(-3.5,-3) M3(-2.5,-3) M4(-1.5,-3) M5(-0.5,-3) M6(0.5,-3) M7(1.5,-3) M8(2.5,-3) M9(3.5,-3) N2(-3.5,-4) N3(-2.5,-4) N4(-1.5,-4) N5(-0.5,-4) N6(0.5,-4) N7(1.5,-4) N8(2.5,-4) N9(3.5,-4) P2(-3.5,-5) P3(-2.5,-5) P4(-1.5,-5) P5(-0.5,-5) P6(0.5,-5) P7(1.5,-5) P8(2.5,-5) P9(3.5,-5) T1(-4.5,-7) T10(4.5,-7) U1(-4.5,-8) U2(-3.5,-8) U9(3.5,-8) U10(4.5,-8)
  silkscreen extent -7.67,-9.05 7.05,9.05, body extent -7.55,-9.55 7.55,9.55, height 0.25
FP-NX3008NBKS,115_TSSOP6-IPC_C [mm]
  rrect29% 0.959x0.342 smd: 1(-0.777,0.65)
  rrect100% 0.959x0.342 smd: 2(-0.777,0) 3(-0.777,-0.65) 4(0.777,-0.65) 5(0.777,0) 6(0.777,0.65)
  silkscreen extent -1.88,-1.25 1.05,1.25, body extent -1.05,-1 1.05,1, height 1.1
FP-RMCF0805ZT0R00_0805-IPC_C [mil]
  rrect10% 37.58x49.69 smd paste+0 mask+0: 1(-30.54,0) 2(30.54,0)
  silkscreen extent -49,-42 49,42, body extent -53,-31 53,31, height 10
FP-S25FL128SAGNFI000_WSON8-MFG [mm]
  rrect100% 0.95x0.45 smd: 1(-3.9,1.905) 2(-3.9,0.635) 3(-3.9,-0.635) 4(-3.9,-1.905) 5(3.9,-1.905) 6(3.9,-0.635) 7(3.9,0.635) 8(3.9,1.905)
  rrect2% 4.75x4.9 smd: 9(0,0)
  silkscreen extent -5.05,-3.05 4.05,3.05, body extent -4.47,-3.23 4.47,3.23, height 0.25
FP-TNPW040215K6BEED_0402-IPC_C [mil]
  rrect21% 18.32x18.6 smd: 1(-15.89,0) 2(15.89,0)
  silkscreen extent -25,-27 25,27, body extent -29,-15 29,15, height 10
Harwin_M7582-05 [mil] "Single Operation 2.54mm Pitch Open Top Jumper Socket"
  body extent -98,-47 98,47, height 236
Keystone5001 [mil] "For Keystone 500x miniature loop terminals"
  round 80 hole 40: 1(0,0)
  silkscreen extent -52,-52 52,52, body extent -49,-49 49,49, height 182
Keystone_1902C [mil] "Hex Standoff, 4-40 threaded, nylon"
  round 1 on Mech4: 0(0,0)
  body extent -145,-126 146,126, height 501
Label_650x200 [mil] "Thermal Transfer Label"
  round 1 on Mech13: 0(0,0)
  silkscreen extent -325,-100 325,100, body extent -325,-100 325,100, height 1
Memory_EJ508A [mm] "Power Jack, 2.1x5.5mm, R/A, TH"
  rrect50% 4.1x1.55 hole 1.02 square: 1(0,2.91)
  oval 3.55x1.3 hole 0.76 square: 2(0,-3.25)
  oval 1.3x3.55 hole 0.76 square: 3(4.55,0)
  silkscreen extent -4.4,-10.74 4.4,3.16, body extent -4.4,-10.74 4.7,3.68, height 10.85
Molex_0022284033 [mm] "Header, 2.54mm, 3x1, TH"
  rect 1.55x1.55 hole 1.02: 1(-2.54,0)
  round 1.55 hole 1.02: 2(0,0) 3(2.54,0)
  silkscreen extent -3.81,-1.24 3.81,1.5, body extent -3.81,-1.24 3.81,1.24, height 8.4
MSS1210 [mm] "Coilcraft MSS1210 series"
  rect 3x5.5 smd: 1(-4.75,0) 2(4.75,0)
  silkscreen extent -6.3,-6.3 6.3,6.3, body extent -6.15,-6.15 6.15,6.15, height 10.2
"NY PMS 440 0025 PH" [mm] "4-40 nylon screw and mounting hole"
  round 8 hole 3.2: 1(0,0)
  body extent -3.3,-3.3 3.3,3.3, height 2.69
